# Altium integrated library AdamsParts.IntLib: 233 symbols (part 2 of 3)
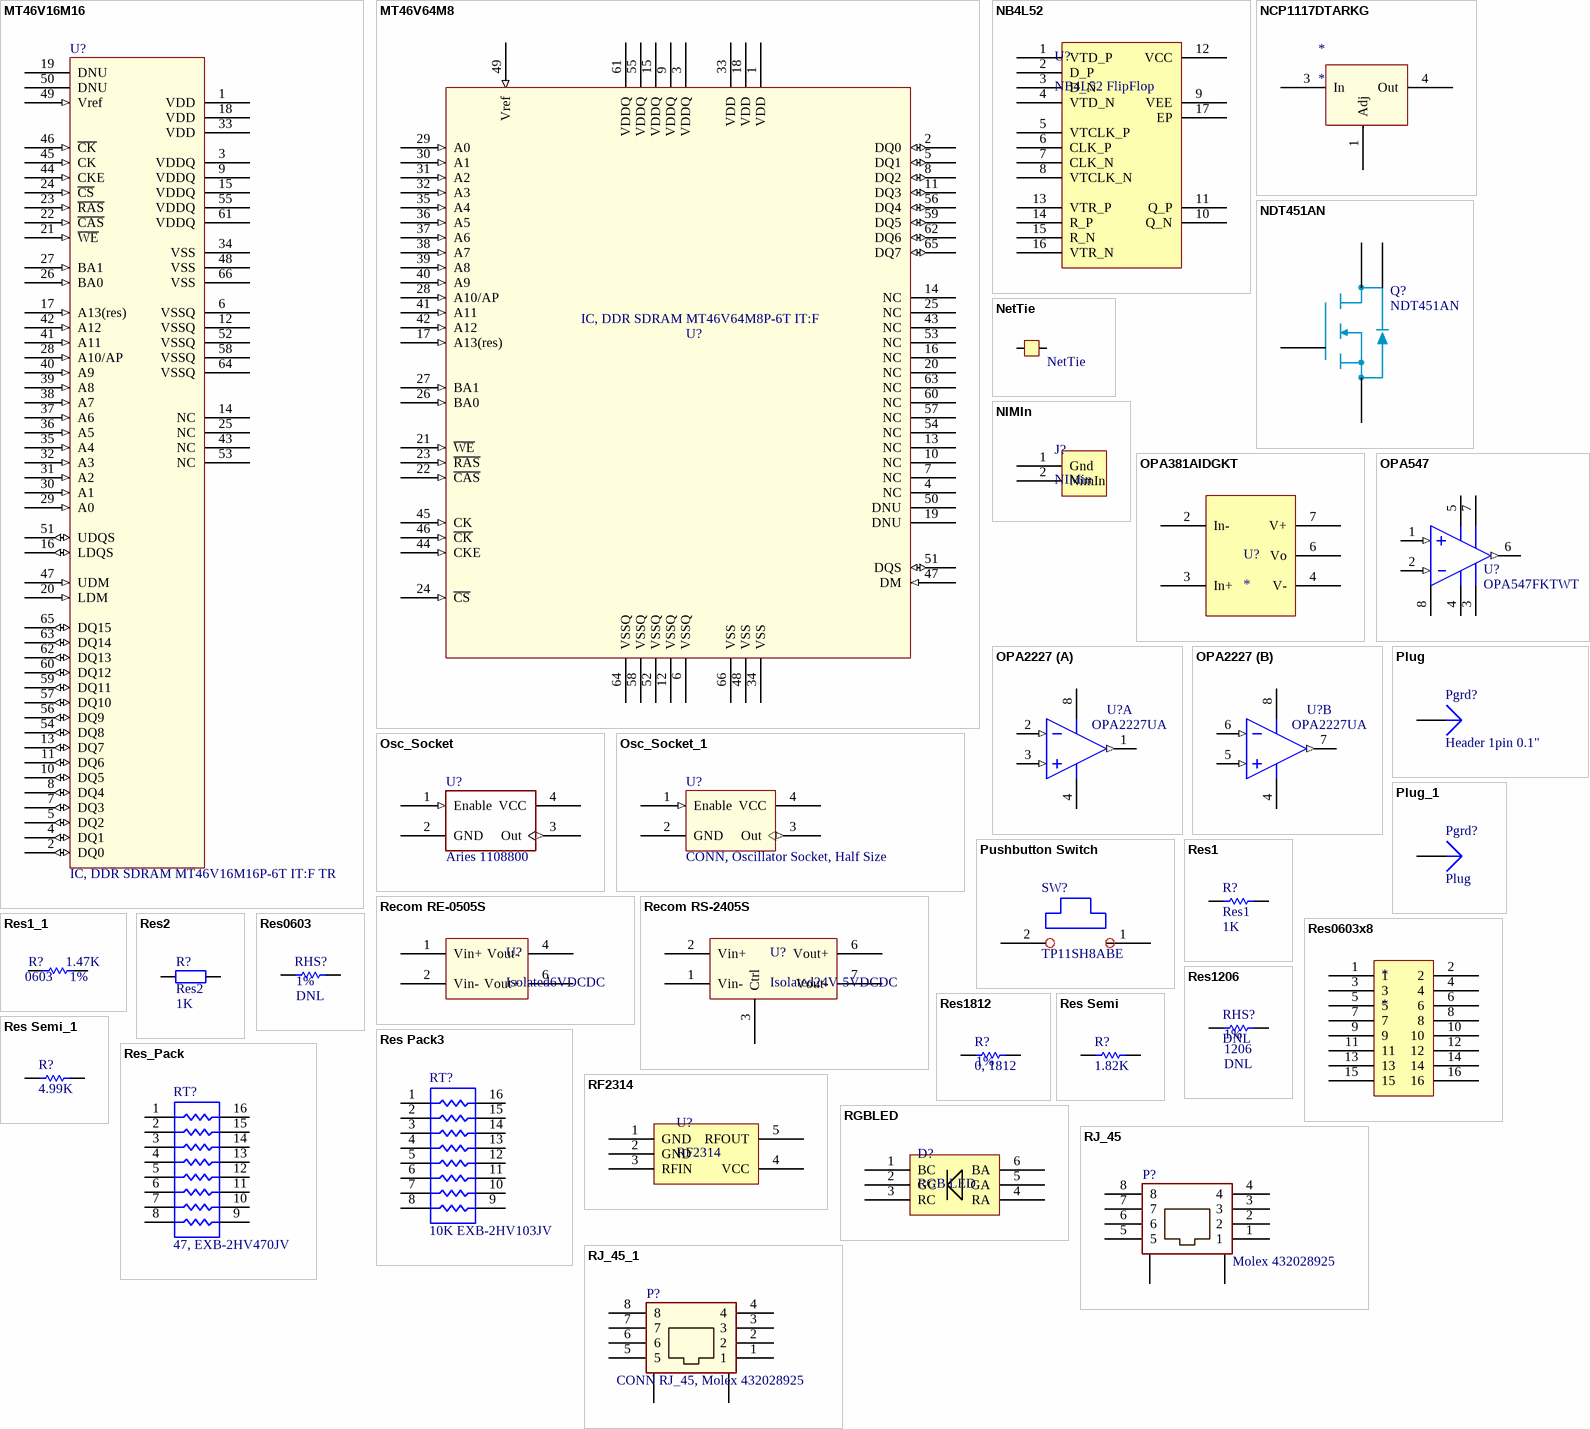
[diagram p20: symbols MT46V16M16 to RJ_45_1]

## OPA547
designator U?, comment OPA547FKTWT
Amp, High-Voltage, High-Current Op Amp; Manufacturer: Texas Instruments
footprint D2PAK-7PIN
pins: 1 IN+ (in), 2 IN- (in), 3 Ilim, 4 Vss (power), 5 Vcc (power), 6 OUT (out), 7 E/S, 8 SH (power)

## OPA2227
designator U?, comment OPA2227UA
Amp, High Precision, Low Noise  Op Amp; Manufacturer: Texas Instruments
footprint SO8
part A pins: 1 OUT (out), 2 IN- (in), 3 IN+ (in), 4 GND (power), 8 VDD (power)
part B pins: 4 GND (power), 5 IN+ (in), 6 IN- (in), 7 OUT (out), 8 VDD (power)

## Osc_Socket
designator U?, comment Aries 1108800
CONN, Oscillator Socket, Half Size; Manufacturer: Aries Electronics
footprint XTAL-OSC/DIP8 (Footprint not found)
pins: 1 Enable (in), 2 GND (power), 3 Out (out), 4 VCC (power)

## Osc_Socket_1
designator U?, comment CONN, Oscillator Socket, Half Size
1108800 ARIES Oscillator Socket
footprint DIP_Osc
pins: 1 Enable (in), 2 GND (power), 3 Out (out), 4 VCC (power)

## Plug
designator Pgrd?, comment Header 1pin 0.1"
Header, 0.1"  1-Pin straight (Any equivalent - may need to be value added); Manufacturer: Digikey; Manufacturers P/N: A26508-01-ND
footprint PIN1
signal-integrity model Connector
pins: 1

## Plug_1
designator Pgrd?, comment Plug
footprint PIN1 (Connector; Plug)
signal-integrity model Connector
pins: 1

## Pushbutton Switch
designator SW?, comment TP11SH8ABE
Switch, Pushbutton FrontPanel; Manufacturer: C&K Components
footprint TP11SH8ABE
pins: 1, 2

## Recom RE-0505S
designator U?, comment Isolated6VDCDC
Isolated 6V DC-DC
footprint RECOM_DCDC_SIP (DC-DC Converter)
pins: 1 Vin+, 2 Vin-, 4 Vout-, 6 Vout+

## Recom RS-2405S
designator U?, comment Isolated24V-5VDCDC
18-36V input, 5V output
footprint RECOM_RS-2405S (DC-DC Converter)
pins: 1 Vin-, 2 Vin+, 3 Ctrl, 5 NC hidden, 6 Vout+, 7 Vout-, 8 NC hidden

## Res1
designator R?  value 1K
Resistor
simulation model RESISTOR (Resistor)
signal-integrity model Res
footprint Model Name (Footprint not found)
footprint Model Name (Footprint not found)
footprint AXIAL-0.3 (Axial Device, Thru-Hole; 2 Leads; 0.3 in Pin Spacing)
footprint AXIAL-0.4 (Axial Device, Thru-Hole; 2 Leads; 0.4 in Pin Spacing)
footprint AXIAL-0.5 (Axial Device, Thru-Hole; 2 Leads; 0.5 in Pin Spacing)
footprint AXIAL-0.6 (Axial Device, Thru-Hole; 2 Leads; 0.6 in Pin Spacing)
footprint AXIAL-0.7 (Axial Device, Thru-Hole; 2 Leads; 0.7 in Pin Spacing)
footprint AXIAL-0.8 (Axial Device, Thru-Hole; 2 Leads; 0.8 in Pin Spacing)
footprint AXIAL-0.9 (Axial Device, Thru-Hole; 2 Leads; 0.9 in Pin Spacing)
footprint AXIAL-1.0 (Axial Device, Thru-Hole; 2 Leads; 1.0 in Pin Spacing)
footprint Model Name (Footprint not found)
pins: 1, 2

## Res1_1
designator R?, comment 1.47K  Param: 1%  Footprint: 0603
RES 1.47K OHM 1/10W 1% 0603 SMD; Manufacturer: Vishay/Dale; Manufacturers P/N: CRCW06031K47FKEA; Param1: 100ppm/C
simulation model RESISTOR (Resistor)
signal-integrity model Res
footprint 0603
pins: 1, 2

## Res2
designator R?  value 1K
Resistor
footprint AXIAL-0.4 (Axial Device, Thru-Hole; 2 Leads; 0.4 in Pin Spacing)
simulation model RESISTOR (Resistor)
signal-integrity model Res
pins: 1, 2

## Res0603
designator RHS?  value DNL  Param: 1%
Resistor; Param1: 100ppm/C
simulation model RESISTOR (Resistor)
signal-integrity model Res
footprint 0603
footprint 0805
pins: 1, 2

## Res0603x8
designator *
pins: 1, 2, 3, 4, 5, 6, 7, 8, 9, 10, 11, 12, 13, 14, 15, 16

## Res1206
designator RHS?, comment DNL  Param: 1%  Footprint: 1206
Resistor; Param1: 100ppm/C
simulation model RESISTOR (Resistor)
signal-integrity model Res
footprint CR1608-0603M (Chip Resistor; Body 1.6 x 0.8 mm (LxW typ))
footprint 1206
pins: 1, 2

## Res1812
designator R?, comment 0, 1812  Param: 1%
Resistor; Param1: 100ppm/C; Value: DNL
simulation model RESISTOR (Resistor)
signal-integrity model Res
pins: 1, 2

## Res Pack3
designator RT?, comment 10K EXB-2HV103JV
Isolated Resistor Network
footprint SO-G16/Z8.5 (Small Outline; 16 Leads; Body Width 5.6 mm; Pitch 1.27 mm)
simulation model respack_8 (Spice Subcircuit)
footprint 0402_Array_2HV
pins: 1, 2, 3, 4, 5, 6, 7, 8, 9, 10, 11, 12, 13, 14, 15, 16

## Res Semi
designator R?, comment 1.82K
RES 1.82K OHM 1/10W 1% 0603 SMD (or Equivalent); Manufacturer: Vishay/Dale; Manufacturers P/N: CRCW06031K82FKEA
footprint CR1608-0603
simulation model RES (Semiconductor Resistor)
signal-integrity model Res Semi
pins: 1, 2

## Res Semi_1
designator R?, comment 4.99K
Resistor 0603
footprint AXIAL-0.5 (Semiconductor Resistor; 2 Leads)
footprint CR1005-0402 (Chip Resistor; Body 1.1 x 0.5 mm (LxW typ))
footprint CR1608-0603 (Chip Resistor; Body 1.6 x 0.8 mm (LxW typ))
footprint CR2012-0805 (Chip Resistor; Body 2.0 x 1.3 mm (LxW typ))
footprint CR3216-1206 (Chip Resistor; Body 3.2 x 1.6 mm (LxW typ))
simulation model RES (Semiconductor Resistor)
signal-integrity model Res Semi
pins: 1, 2

## Res_Pack
designator RT?, comment 47, EXB-2HV470JV
8x 0402 RES ARRAY 47 OHM 5%  SMD; Manufacturer: Panasonic - ECG
footprint 0402_Array_2HV
pins: 1, 2, 3, 4, 5, 6, 7, 8, 9, 10, 11, 12, 13, 14, 15, 16

## RF2314
designator U?
footprint RF2314 (SOT23, 5-Leads, Body 2.9x3.0mm (max), Pitch 0.95mm, IPC Medium Density)
pins: 1 GND, 2 GND, 3 RFIN, 4 VCC, 5 RFOUT

## RGBLED
designator D?, comment RGB LED
footprint RGBLED
pins: 1 BC, 2 GC, 3 RC, 4 RA, 5 GA, 6 BA

## RJ_45
designator P?, comment Molex 432028925
CONN, RJ45; Manufacturers P/N: 0432028925
footprint RJ45
pins: 1, 2, 3, 4, 5, 6, 7, 8, 9 GND (power), 10 GND (power)

## RJ_45_1
designator P?, comment CONN RJ_45, Molex 432028925
Molex 432028925
footprint RJ45 (Regular network RJ45)
pins: 1, 2, 3, 4, 5, 6, 7, 8, 9 GND (power), 10 GND (power)

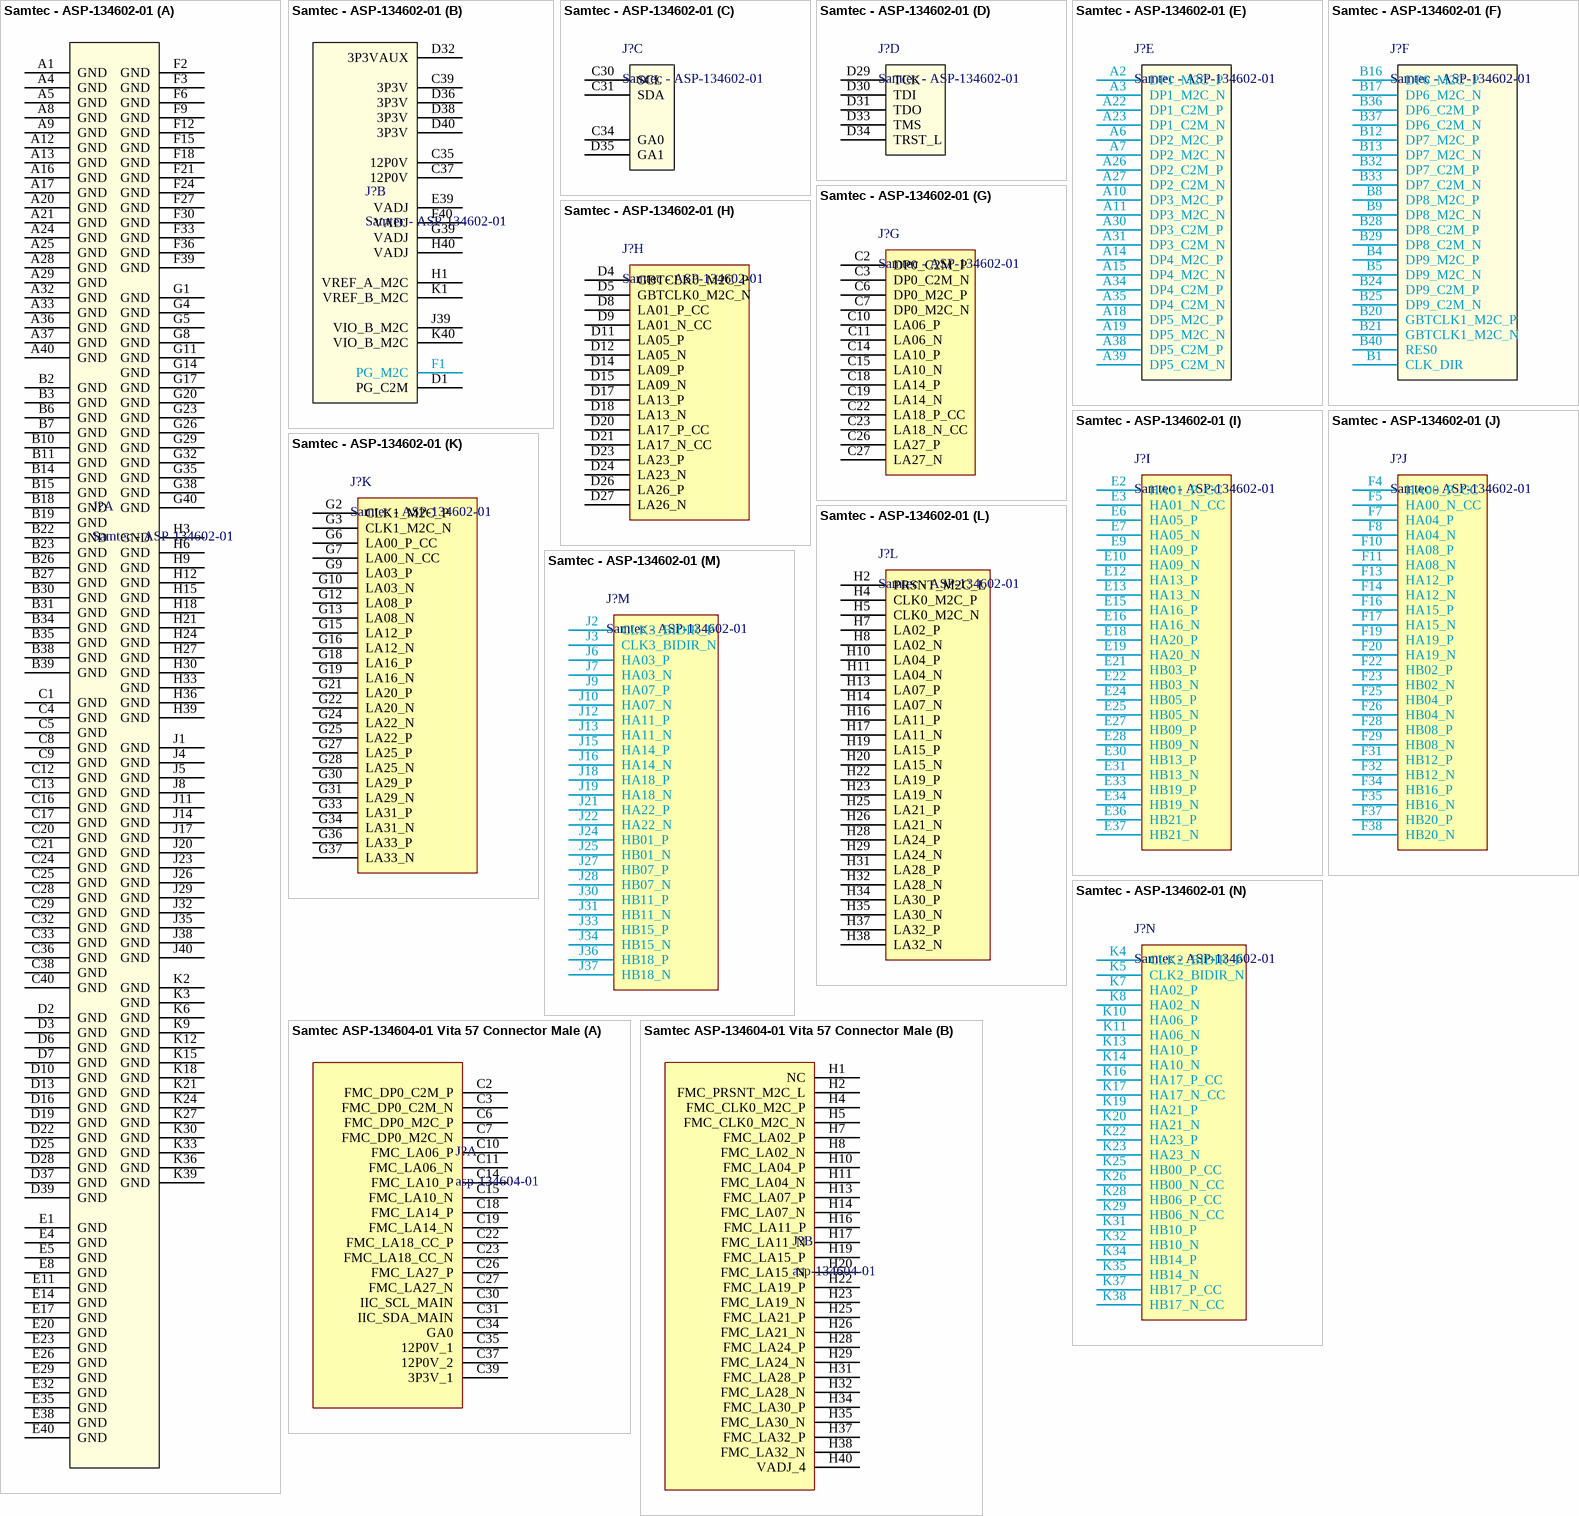
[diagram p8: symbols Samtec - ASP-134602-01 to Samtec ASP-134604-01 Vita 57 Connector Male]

## Samtec - ASP-134602-01
designator J?
footprint FCM-ASP_134602-01 (400pin FCM connector VITA)
part A pins: A1 GND, A4 GND, A5 GND, A8 GND, A9 GND, A12 GND, A13 GND, A16 GND, A17 GND, A20 GND, A21 GND, A24 GND, A25 GND, A28 GND, A29 GND, A32 GND, A33 GND, A36 GND, A37 GND, A40 GND, B2 GND, B3 GND, B6 GND, B7 GND, B10 GND, B11 GND, B14 GND, B15 GND, B18 GND, B19 GND, B22 GND, B23 GND, B26 GND, B27 GND, B30 GND, B31 GND, B34 GND, B35 GND, B38 GND, B39 GND, C1 GND, C4 GND, C5 GND, C8 GND, C9 GND, C12 GND, C13 GND, C16 GND, C17 GND, C20 GND, C21 GND, C24 GND, C25 GND, C28 GND, C29 GND, C32 GND, C33 GND, C36 GND, C38 GND, C40 GND, D2 GND, D3 GND, D6 GND, D7 GND, D10 GND, D13 GND, D16 GND, D19 GND, D22 GND, D25 GND, D28 GND, D37 GND, D39 GND, E1 GND, E4 GND, E5 GND, E8 GND, E11 GND, E14 GND, E17 GND, E20 GND, E23 GND, E26 GND, E29 GND, E32 GND, E35 GND, E38 GND, E40 GND, F2 GND, F3 GND, F6 GND, F9 GND, F12 GND, F15 GND, F18 GND, F21 GND, F24 GND, F27 GND, F30 GND, F33 GND, F36 GND, F39 GND, G1 GND, G4 GND, G5 GND, G8 GND, G11 GND, G14 GND, G17 GND, G20 GND, G23 GND, G26 GND, G29 GND, G32 GND, G35 GND, G38 GND, G40 GND, H3 GND, H6 GND, H9 GND, H12 GND, H15 GND, H18 GND, H21 GND, H24 GND, H27 GND, H30 GND, H33 GND, H36 GND, H39 GND, J1 GND, J4 GND, J5 GND, J8 GND, J11 GND, J14 GND, J17 GND, J20 GND, J23 GND, J26 GND, J29 GND, J32 GND, J35 GND, J38 GND, J40 GND, K2 GND, K3 GND, K6 GND, K9 GND, K12 GND, K15 GND, K18 GND, K21 GND, K24 GND, K27 GND, K30 GND, K33 GND, K36 GND, K39 GND
part B pins: C35 12P0V, C37 12P0V, C39 3P3V, D1 PG_C2M, D32 3P3VAUX, D36 3P3V, D38 3P3V, D40 3P3V, E39 VADJ, F1 PG_M2C, F40 VADJ, G39 VADJ, H1 VREF_A_M2C, H40 VADJ, J39 VIO_B_M2C, K1 VREF_B_M2C, K40 VIO_B_M2C
part C pins: C30 SCL, C31 SDA, C34 GA0, D35 GA1
part D pins: D29 TCK, D30 TDI, D31 TDO, D33 TMS, D34 TRST_L
part E pins: A2 DP1_M2C_P, A3 DP1_M2C_N, A6 DP2_M2C_P, A7 DP2_M2C_N, A10 DP3_M2C_P, A11 DP3_M2C_N, A14 DP4_M2C_P, A15 DP4_M2C_N, A18 DP5_M2C_P, A19 DP5_M2C_N, A22 DP1_C2M_P, A23 DP1_C2M_N, A26 DP2_C2M_P, A27 DP2_C2M_N, A30 DP3_C2M_P, A31 DP3_C2M_N, A34 DP4_C2M_P, A35 DP4_C2M_N, A38 DP5_C2M_P, A39 DP5_C2M_N
part F pins: B1 CLK_DIR, B4 DP9_M2C_P, B5 DP9_M2C_N, B8 DP8_M2C_P, B9 DP8_M2C_N, B12 DP7_M2C_P, B13 DP7_M2C_N, B16 DP6_M2C_P, B17 DP6_M2C_N, B20 GBTCLK1_M2C_P, B21 GBTCLK1_M2C_N, B24 DP9_C2M_P, B25 DP9_C2M_N, B28 DP8_C2M_P, B29 DP8_C2M_N, B32 DP7_C2M_P, B33 DP7_C2M_N, B36 DP6_C2M_P, B37 DP6_C2M_N, B40 RES0
part G pins: C2 DP0_C2M_P, C3 DP0_C2M_N, C6 DP0_M2C_P, C7 DP0_M2C_N, C10 LA06_P, C11 LA06_N, C14 LA10_P, C15 LA10_N, C18 LA14_P, C19 LA14_N, C22 LA18_P_CC, C23 LA18_N_CC, C26 LA27_P, C27 LA27_N
part H pins: D4 GBTCLK0_M2C_P, D5 GBTCLK0_M2C_N, D8 LA01_P_CC, D9 LA01_N_CC, D11 LA05_P, D12 LA05_N, D14 LA09_P, D15 LA09_N, D17 LA13_P, D18 LA13_N, D20 LA17_P_CC, D21 LA17_N_CC, D23 LA23_P, D24 LA23_N, D26 LA26_P, D27 LA26_N
part I pins: E2 HA01_P_CC, E3 HA01_N_CC, E6 HA05_P, E7 HA05_N, E9 HA09_P, E10 HA09_N, E12 HA13_P, E13 HA13_N, E15 HA16_P, E16 HA16_N, E18 HA20_P, E19 HA20_N, E21 HB03_P, E22 HB03_N, E24 HB05_P, E25 HB05_N, E27 HB09_P, E28 HB09_N, E30 HB13_P, E31 HB13_N, E33 HB19_P, E34 HB19_N, E36 HB21_P, E37 HB21_N
part J pins: F4 HA00_P_CC, F5 HA00_N_CC, F7 HA04_P, F8 HA04_N, F10 HA08_P, F11 HA08_N, F13 HA12_P, F14 HA12_N, F16 HA15_P, F17 HA15_N, F19 HA19_P, F20 HA19_N, F22 HB02_P, F23 HB02_N, F25 HB04_P, F26 HB04_N, F28 HB08_P, F29 HB08_N, F31 HB12_P, F32 HB12_N, F34 HB16_P, F35 HB16_N, F37 HB20_P, F38 HB20_N
part K pins: G2 CLK1_M2C_P, G3 CLK1_M2C_N, G6 LA00_P_CC, G7 LA00_N_CC, G9 LA03_P, G10 LA03_N, G12 LA08_P, G13 LA08_N, G15 LA12_P, G16 LA12_N, G18 LA16_P, G19 LA16_N, G21 LA20_P, G22 LA20_N, G24 LA22_N, G25 LA22_P, G27 LA25_P, G28 LA25_N, G30 LA29_P, G31 LA29_N, G33 LA31_P, G34 LA31_N, G36 LA33_P, G37 LA33_N
part L pins: H2 PRSNT_M2C_L, H4 CLK0_M2C_P, H5 CLK0_M2C_N, H7 LA02_P, H8 LA02_N, H10 LA04_P, H11 LA04_N, H13 LA07_P, H14 LA07_N, H16 LA11_P, H17 LA11_N, H19 LA15_P, H20 LA15_N, H22 LA19_P, H23 LA19_N, H25 LA21_P, H26 LA21_N, H28 LA24_P, H29 LA24_N, H31 LA28_P, H32 LA28_N, H34 LA30_P, H35 LA30_N, H37 LA32_P, H38 LA32_N
part M pins: J2 CLK3_BIDIR_P, J3 CLK3_BIDIR_N, J6 HA03_P, J7 HA03_N, J9 HA07_P, J10 HA07_N, J12 HA11_P, J13 HA11_N, J15 HA14_P, J16 HA14_N, J18 HA18_P, J19 HA18_N, J21 HA22_P, J22 HA22_N, J24 HB01_P, J25 HB01_N, J27 HB07_P, J28 HB07_N, J30 HB11_P, J31 HB11_N, J33 HB15_P, J34 HB15_N, J36 HB18_P, J37 HB18_N
part N pins: K4 CLK2_BIDIR_P, K5 CLK2_BIDIR_N, K7 HA02_P, K8 HA02_N, K10 HA06_P, K11 HA06_N, K13 HA10_P, K14 HA10_N, K16 HA17_P_CC, K17 HA17_N_CC, K19 HA21_P, K20 HA21_N, K22 HA23_P, K23 HA23_N, K25 HB00_P_CC, K26 HB00_N_CC, K28 HB06_P_CC, K29 HB06_N_CC, K31 HB10_P, K32 HB10_N, K34 HB14_P, K35 HB14_N, K37 HB17_P_CC, K38 HB17_N_CC

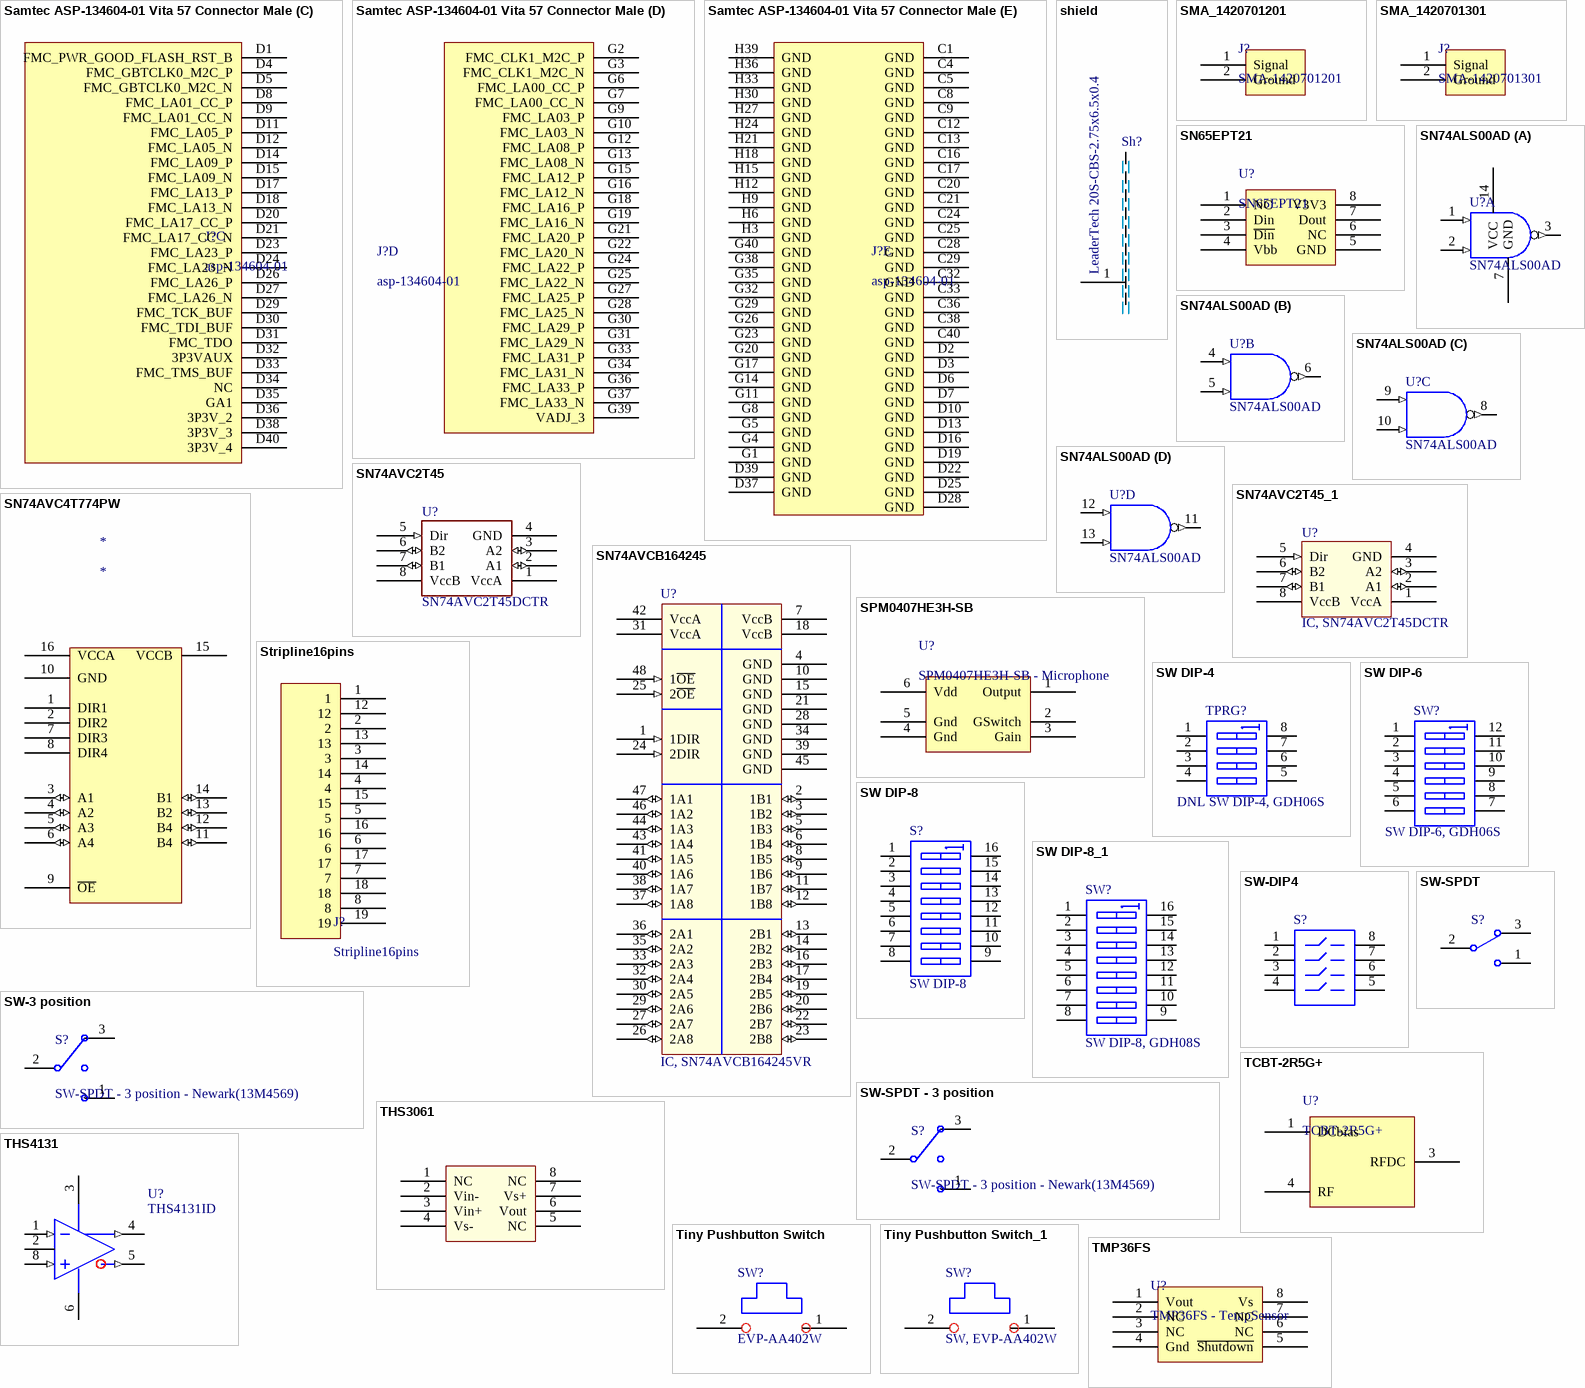
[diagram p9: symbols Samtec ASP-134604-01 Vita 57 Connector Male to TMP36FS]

## Samtec ASP-134604-01 Vita 57 Connector Male
designator J?, comment asp-134604-01
footprint FCM-ASP_134603-01 (160pin FCM connector VITA)
part A pins: C2 FMC_DP0_C2M_P, C3 FMC_DP0_C2M_N, C6 FMC_DP0_M2C_P, C7 FMC_DP0_M2C_N, C10 FMC_LA06_P, C11 FMC_LA06_N, C14 FMC_LA10_P, C15 FMC_LA10_N, C18 FMC_LA14_P, C19 FMC_LA14_N, C22 FMC_LA18_CC_P, C23 FMC_LA18_CC_N, C26 FMC_LA27_P, C27 FMC_LA27_N, C30 IIC_SCL_MAIN, C31 IIC_SDA_MAIN, C34 GA0, C35 12P0V_1, C37 12P0V_2, C39 3P3V_1
part B pins: H1 NC, H2 FMC_PRSNT_M2C_L, H4 FMC_CLK0_M2C_P, H5 FMC_CLK0_M2C_N, H7 FMC_LA02_P, H8 FMC_LA02_N, H10 FMC_LA04_P, H11 FMC_LA04_N, H13 FMC_LA07_P, H14 FMC_LA07_N, H16 FMC_LA11_P, H17 FMC_LA11_N, H19 FMC_LA15_P, H20 FMC_LA15_N, H22 FMC_LA19_P, H23 FMC_LA19_N, H25 FMC_LA21_P, H26 FMC_LA21_N, H28 FMC_LA24_P, H29 FMC_LA24_N, H31 FMC_LA28_P, H32 FMC_LA28_N, H34 FMC_LA30_P, H35 FMC_LA30_N, H37 FMC_LA32_P, H38 FMC_LA32_N, H40 VADJ_4
part C pins: D1 FMC_PWR_GOOD_FLASH_RST_B, D4 FMC_GBTCLK0_M2C_P, D5 FMC_GBTCLK0_M2C_N, D8 FMC_LA01_CC_P, D9 FMC_LA01_CC_N, D11 FMC_LA05_P, D12 FMC_LA05_N, D14 FMC_LA09_P, D15 FMC_LA09_N, D17 FMC_LA13_P, D18 FMC_LA13_N, D20 FMC_LA17_CC_P, D21 FMC_LA17_CC_N, D23 FMC_LA23_P, D24 FMC_LA23_N, D26 FMC_LA26_P, D27 FMC_LA26_N, D29 FMC_TCK_BUF, D30 FMC_TDI_BUF, D31 FMC_TDO, D32 3P3VAUX, D33 FMC_TMS_BUF, D34 NC, D35 GA1, D36 3P3V_2, D38 3P3V_3, D40 3P3V_4
part D pins: G2 FMC_CLK1_M2C_P, G3 FMC_CLK1_M2C_N, G6 FMC_LA00_CC_P, G7 FMC_LA00_CC_N, G9 FMC_LA03_P, G10 FMC_LA03_N, G12 FMC_LA08_P, G13 FMC_LA08_N, G15 FMC_LA12_P, G16 FMC_LA12_N, G18 FMC_LA16_P, G19 FMC_LA16_N, G21 FMC_LA20_P, G22 FMC_LA20_N, G24 FMC_LA22_P, G25 FMC_LA22_N, G27 FMC_LA25_P, G28 FMC_LA25_N, G30 FMC_LA29_P, G31 FMC_LA29_N, G33 FMC_LA31_P, G34 FMC_LA31_N, G36 FMC_LA33_P, G37 FMC_LA33_N, G39 VADJ_3
part E pins: C1 GND, C4 GND, C5 GND, C8 GND, C9 GND, C12 GND, C13 GND, C16 GND, C17 GND, C20 GND, C21 GND, C24 GND, C25 GND, C28 GND, C29 GND, C32 GND, C33 GND, C36 GND, C38 GND, C40 GND, D2 GND, D3 GND, D6 GND, D7 GND, D10 GND, D13 GND, D16 GND, D19 GND, D22 GND, D25 GND, D28 GND, D37 GND, D39 GND, G1 GND, G4 GND, G5 GND, G8 GND, G11 GND, G14 GND, G17 GND, G20 GND, G23 GND, G26 GND, G29 GND, G32 GND, G35 GND, G38 GND, G40 GND, H3 GND, H6 GND, H9 GND, H12 GND, H15 GND, H18 GND, H21 GND, H24 GND, H27 GND, H30 GND, H33 GND, H36 GND, H39 GND

## shield
designator Sh?, comment LeaderTech 20S-CBS-2.75x6.5x0.4
Grounded RF Shield
footprint Shield base
pins: 1

## SMA_1420701201
designator J?, comment SMA-1420701201
Vertical SMA
footprint SMA-1420701301 (SMA 1420701301 Ghz Connector)
footprint SMA-1420701201 (SMA 1420701201 Ghz Connector)
pins: 1 Signal, 2 Ground

## SMA_1420701301
designator J?, comment SMA-1420701301
Horizontal SMA
footprint SMA-1420701301 (SMA 1420701301 Ghz Connector)
pins: 1 Signal, 2 Ground

## SN65EPT21
designator U?
footprint SO8/L200
pins: 1 NC, 2 Din, 3 ~{Din}, 4 Vbb, 5 GND, 6 NC, 7 Dout, 8 V3V3

## SN74ALS00AD
designator U?
Quadruple 2-Input Positive-NAND Gate
footprint D014_N (SOIC, 14-Leads, Body 8.7x3.9mm, Pitch 1.27mm, IPC Medium Density)
footprint D014_L (SOIC, 14-Leads, Body 8.7x3.9mm, Pitch 1.27mm, IPC High Density)
footprint D014_M (SOIC, 14-Leads, Body 8.7x3.9mm, Pitch 1.27mm, IPC Low Density)
signal-integrity model SN74ALS00AD
part A pins: 1 A (in), 2 B (in), 3 Y (out), 7 GND, 14 VCC
part B pins: 4 A (in), 5 B (in), 6 Y (out)
part C pins: 8 Y (out), 9 A (in), 10 B (in)
part D pins: 11 Y (out), 12 A (in), 13 B (in)

## SN74AVC2T45
designator U?, comment SN74AVC2T45DCTR
Transceiver, Dual-bit Dual-supply Bus; Manufacturer: Texas Instruments
footprint SM8 (Footprint not found)
pins: 1 VccA (power), 2 A1 (io), 3 A2 (io), 4 GND (power), 5 Dir (in), 6 B2 (io), 7 B1 (io), 8 VccB (power)

## SN74AVC2T45_1
designator U?, comment IC, SN74AVC2T45DCTR
Dual-bit Dual-supply Bus Transceiver
footprint TSSO3x5-G8/X.35 (Shrink Small Outline; 8 Leads; Body Width 3 mm; Pitch 0.65 mm)
pins: 1 VccA (power), 2 A1 (io), 3 A2 (io), 4 GND (power), 5 Dir (in), 6 B2 (io), 7 B1 (io), 8 VccB (power)

## SN74AVC4T774PW
designator *
footprint TSSOP16_M (TSOP, 16-Leads, Body 5x4.4mm, Pitch 0.65mm, IPC Low Density)
pins: 1 DIR1, 2 DIR2, 3 A1 (io), 4 A2 (io), 5 A3 (io), 6 A4 (io), 7 DIR3, 8 DIR4, 9 ~{OE}, 10 GND, 11 B4 (io), 12 B4 (io), 13 B2 (io), 14 B1 (io), 15 VCCB, 16 VCCA

## SN74AVCB164245
designator U?, comment IC, SN74AVCB164245VR
16-Bit Dual-Supply Bus Transceiver with CVT and 3-state
footprint DGV048 (Shrink Small Outline; 48 Leads; Body Width 4.4 mm; Pitch 0.4 mm)
pins: 1 1DIR (in), 2 1B1 (io), 3 1B2 (io), 4 GND (power), 5 1B3 (io), 6 1B4 (io), 7 VccB (power), 8 1B5 (io), 9 1B6 (io), 10 GND (power), 11 1B7 (io), 12 1B8 (io), 13 2B1 (io), 14 2B2 (io), 15 GND (power), 16 2B3 (io), 17 2B4 (io), 18 VccB (power), 19 2B5 (io), 20 2B6 (io), 21 GND (power), 22 2B7 (io), 23 2B8 (io), 24 2DIR (in), 25 2~{OE} (in), 26 2A8 (io), 27 2A7 (io), 28 GND (power), 29 2A6 (io), 30 2A5 (io), 31 VccA (power), 32 2A4 (io), 33 2A3 (io), 34 GND (power), 35 2A2 (io), 36 2A1 (io), 37 1A8 (io), 38 1A7 (io), 39 GND (power), 40 1A6 (io), 41 1A5 (io), 42 VccA (power), 43 1A4 (io), 44 1A3 (io), 45 GND (power), 46 1A2 (io), 47 1A1 (io), 48 1~{OE} (in)

## SPM0407HE3H-SB
designator U?, comment SPM0407HE3H-SB - Microphone
footprint SPM0407HE3H-SB
pins: 1 Output, 2 GSwitch, 3 Gain, 4 Gnd, 5 Gnd, 6 Vdd

## Stripline16pins
designator J?
footprint Stripline16pins (Stripline 16pins)
pins: 1, 2, 3, 4, 5, 6, 7, 8, 12, 13, 14, 15, 16, 17, 18, 19

## SW DIP-4
designator TPRG?, comment DNL SW DIP-4, GDH06S
DIP Switch, 4 Position, SPST
footprint SO-G8 (Small Outline; 8 Leads; Body Width 3.9 mm; Pitch 1.27 mm)
simulation model dpsw4 (Spice Subcircuit)
pins: 1 A1, 2 A2, 3 A3, 4 A4, 5 B4, 6 B3, 7 B2, 8 B1

## SW DIP-6
designator SW?, comment SW DIP-6, GDH06S
DIP Switch, 6 Position, SPST
footprint DIP-12/SW (DIP Switch; 12 Leads)
simulation model dpsw6 (Spice Subcircuit)
footprint DIP_SW_SM6POS (6-position DIP switch)
pins: 1 A1, 2 A2, 3 A3, 4 A4, 5 A5, 6 A6, 7 B6, 8 B5, 9 B4, 10 B3, 11 B2, 12 B1

## SW DIP-8
designator S?
DIP Switch, 8 Position, SPST; Manufacturer: Grayhill Inc; Manufacturers P/N: 97c08st
footprint DIP_SW_8WAY_SMD (DIP Switch; 16 Leads)
simulation model dpsw8 (Spice Subcircuit)
footprint SW-SO16 (Footprint not found)
pins: 1 A1, 2 A2, 3 A3, 4 A4, 5 A5, 6 A6, 7 A7, 8 A8, 9 B8, 10 B7, 11 B6, 12 B5, 13 B4, 14 B3, 15 B2, 16 B1

## SW DIP-8_1
designator SW?, comment SW DIP-8, GDH08S
DIP Switch, 8 Position, SPST
footprint DIP_SW_8WAY_SMD (DIP Switch; 16 Leads)
simulation model dpsw8 (Spice Subcircuit)
pins: 1 A1, 2 A2, 3 A3, 4 A4, 5 A5, 6 A6, 7 A7, 8 A8, 9 B8, 10 B7, 11 B6, 12 B5, 13 B4, 14 B3, 15 B2, 16 B1

## SW-3 position
designator S?, comment SW-SPDT - 3 position - Newark(13M4569)
3 Pos Toggle Switch
footprint SW-3Pos
pins: 1, 2, 3

## SW-DIP4
designator S?
DIP Switch
footprint DIP8SM (Surface Mount DIP 8 package)
pins: 1, 2, 3, 4, 5, 6, 7, 8

## SW-SPDT
designator S?
SPDT Subminiature Toggle Switch, Right Angle Mounting, Vertical Actuation
footprint TL36WW15050 (SPDT Subminiature Toggle Switch, Right Angle Mounting, Vertical Actuation)
pins: 1, 2, 3

## SW-SPDT - 3 position
designator S?, comment SW-SPDT - 3 position - Newark(13M4569)
SPDT Subminiature Toggle Switch, Right Angle Mounting, Vertical Actuation
footprint TL36WW15050 (SPDT Subminiature Toggle Switch, Right Angle Mounting, Vertical Actuation)
footprint HDR1X3
pins: 1, 2, 3

## TCBT-2R5G+
designator U?
Minicircuits 50 Ohm 20-2500Mhz RF Tee
footprint TCBT-2R5G+ (Minicircuits Bias-Tee 50 Ohm 20-2500MHz)
pins: 1 DCbias, 3 RFDC, 4 RF

## THS3061
designator *
footprint SO8/L200
pins: 1 NC, 2 Vin-, 3 Vin+, 4 Vs-, 5 NC, 6 Vout, 7 Vs+, 8 NC

## THS4131
designator U?, comment THS4131ID
Amp, FULLY-DIFFERENTIAL Op Amp; Manufacturer: Texas Instruments
simulation model ths4131 (SUBCKT)
footprint SO-G8 (SOIC)
pins: 1 (in), 2, 3 (power), 4 (out), 5 (out), 6 (power), 7 NC hidden, 8 (in)

## Tiny Pushbutton Switch
designator SW?, comment EVP-AA402W
Switch, SM pushbutton SPST; Manufacturer: Panasonic - ECG
footprint EVPAA
pins: 1, 2

## Tiny Pushbutton Switch_1
designator SW?, comment SW, EVP-AA402W
Switch, SM pushbutton SPST
footprint TP11 (Vertical 90 degree front panel pushbutton)
footprint EVPAA
footprint TP11SH8ABE
pins: 1, 2

## TMP36FS
designator U?, comment TMP36FS - TempSensor
footprint SO8/L200
pins: 1 Vout, 2 NC, 3 NC, 4 Gnd, 5 ~{Shutdown}, 6 NC, 7 NC, 8 Vs

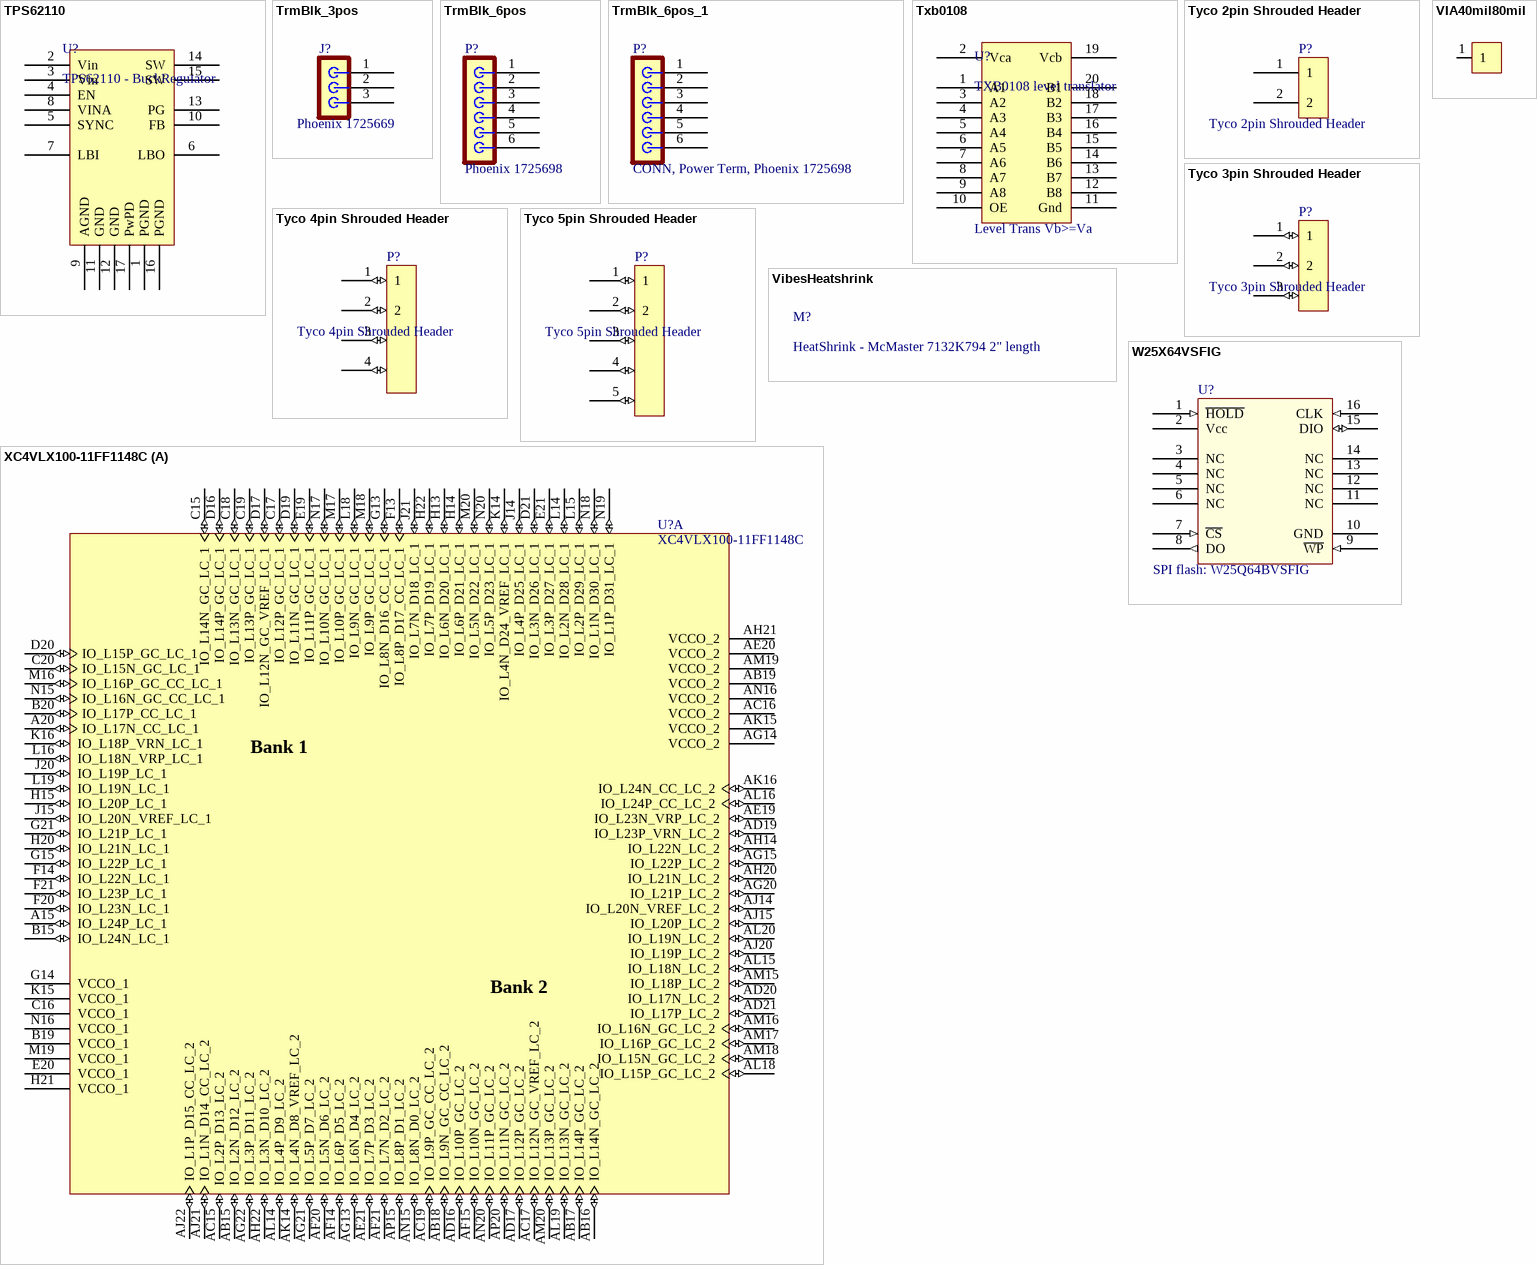
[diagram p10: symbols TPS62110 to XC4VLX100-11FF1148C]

## TPS62110
designator U?, comment TPS62110 - BuckRegulator
Buck Converter 1Mhz 1.5A
footprint RSA (S-PQFP-N16) (QFN, 16-Leads, Body 4.2x4.2mm (max), Pitch 0.65mm, IPC Medium Density)
pins: 1 PGND, 2 Vin, 3 Vin, 4 EN, 5 SYNC, 6 LBO, 7 LBI, 8 VINA, 9 AGND, 10 FB, 11 GND, 12 GND, 13 PG, 14 SW, 15 SW, 16 PGND, 17 PwPD

## TrmBlk_3pos
designator J?, comment Phoenix 1725669
CONN, MPT 0.5/3-2.54 Terminal Block; Manufacturer: Phoenix Contact; Manufacturers P/N: 1725698
footprint PHOENIX_1725669-3PIN (Footprint not found)
pins: 1, 2, 3

## TrmBlk_6pos
designator P?, comment Phoenix 1725698
CONN, MPT 0.5/6-2.54 Terminal Block; Manufacturer: Phoenix Contact
footprint TrmBlk6
pins: 1, 2, 3, 4, 5, 6

## TrmBlk_6pos_1
designator P?, comment CONN, Power Term, Phoenix 1725698
MPT 0.5/6-2.54 Terminal Block
footprint TrmBlk6 (Phoenix 6-Pos Terminal Block)
pins: 1, 2, 3, 4, 5, 6

## Txb0108
designator U?, comment TXB0108 level translator
8bit level translator - Bidirectional without directional control
footprint TSOP65P640X120-20N (TSOP, 20-Leads, Body 6.6x4.5mm (max), Pitch 0.65mm, IPC Medium Density)
pins: 1 A1, 2 Vca, 3 A2, 4 A3, 5 A4, 6 A5, 7 A6, 8 A7, 9 A8, 10 OE, 11 Gnd, 12 B8, 13 B7, 14 B6, 15 B5, 16 B4, 17 B3, 18 B2, 19 Vcb, 20 B1

## Tyco 2pin Shrouded Header
designator P?
footprint Tyco 2pin Shrouded Header
pins: 1, 2

## Tyco 3pin Shrouded Header
designator P?
footprint Tyco 3pin Shrouded Header
pins: 1 (io), 2 (io), 3 (io)

## Tyco 4pin Shrouded Header
designator P?
footprint Tyco 4pin Shrouded Header
pins: 1 (io), 2 (io), 3 (io), 4 (io)

## Tyco 5pin Shrouded Header
designator P?
footprint Tyco 5pin Shrouded Header
pins: 1 (io), 2 (io), 3 (io), 4 (io), 5 (io)

## VIA40mil80mil
designator V?  (value not drawn)
footprint VIA40mil80mil (Via with 40mil hole and 80mil diameter)
pins: 1

## VibesHeatshrink
designator M?, comment HeatShrink - McMaster 7132K794 2" length
Vibes board Heat Shrink

## W25X64VSFIG
designator U?, comment SPI flash: W25Q64BVSFIG
Manufacturer: Winbond Electronics
footprint SOIC127P1030X264-16N (SOIC, 16-Leads, Body 10.5x7.6mm (max), Pitch 1.27mm, IPC Medium Density)
footprint sol16
pins: 1 ~{HOLD} (in), 2 Vcc (power), 3 NC (hiz), 4 NC (hiz), 5 NC (hiz), 6 NC (hiz), 7 ~{CS} (in), 8 DO (out), 9 ~{WP} (in), 10 GND (power), 11 NC (hiz), 12 NC (hiz), 13 NC (hiz), 14 NC (hiz), 15 DIO (io), 16 CLK (in)

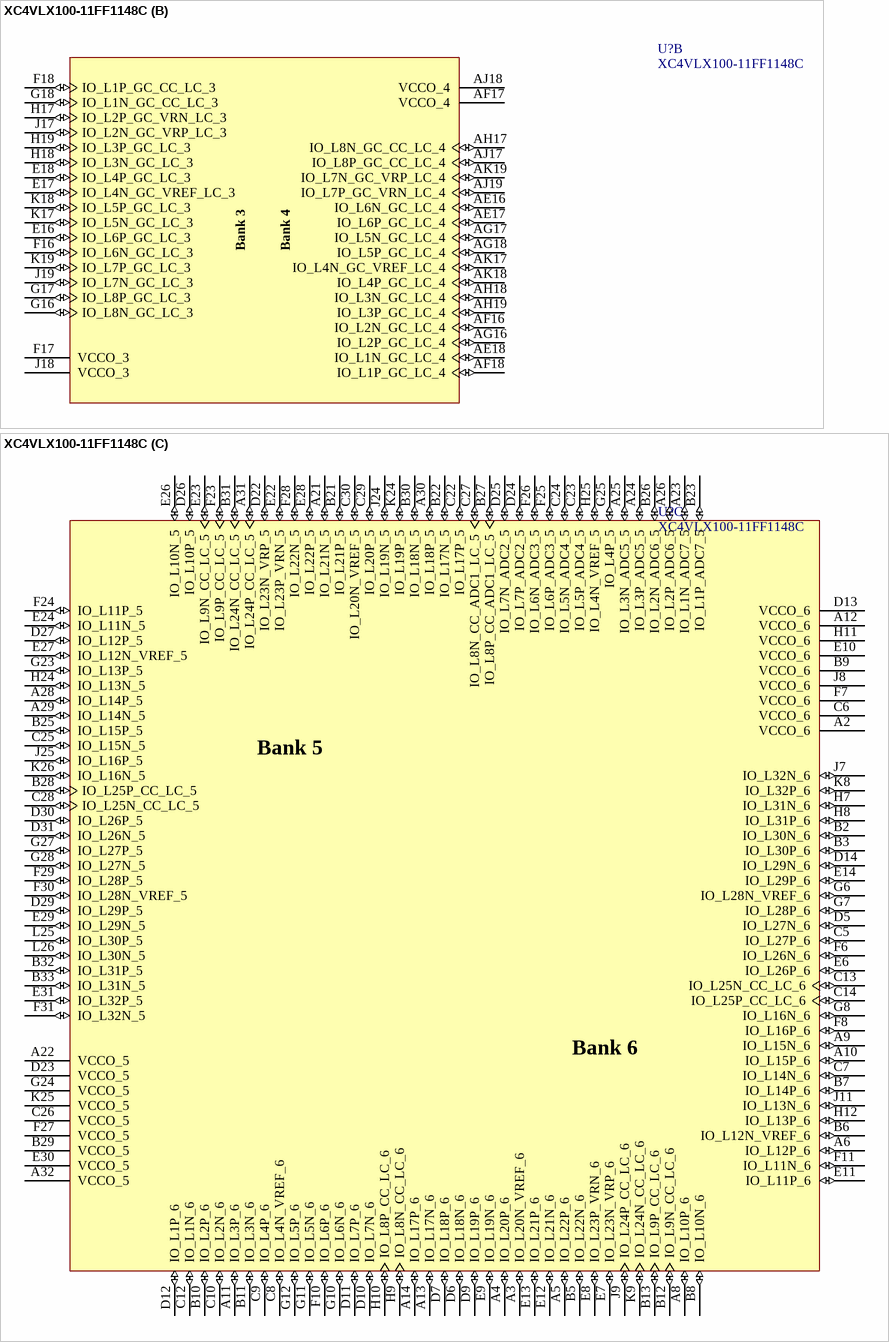
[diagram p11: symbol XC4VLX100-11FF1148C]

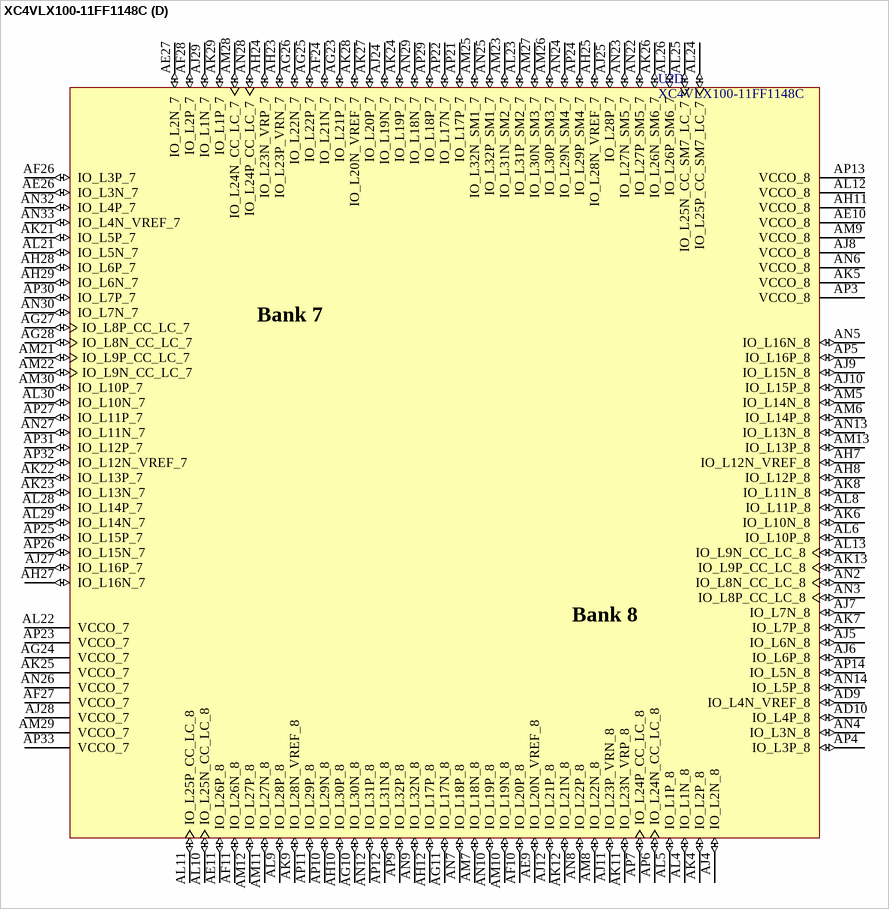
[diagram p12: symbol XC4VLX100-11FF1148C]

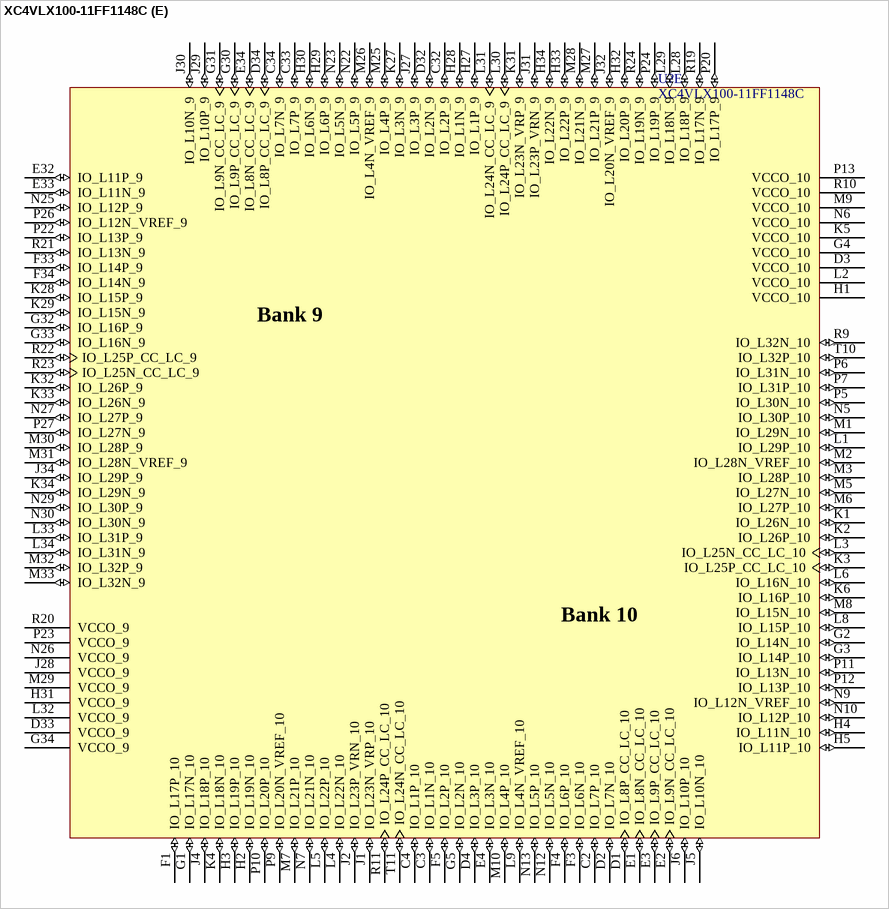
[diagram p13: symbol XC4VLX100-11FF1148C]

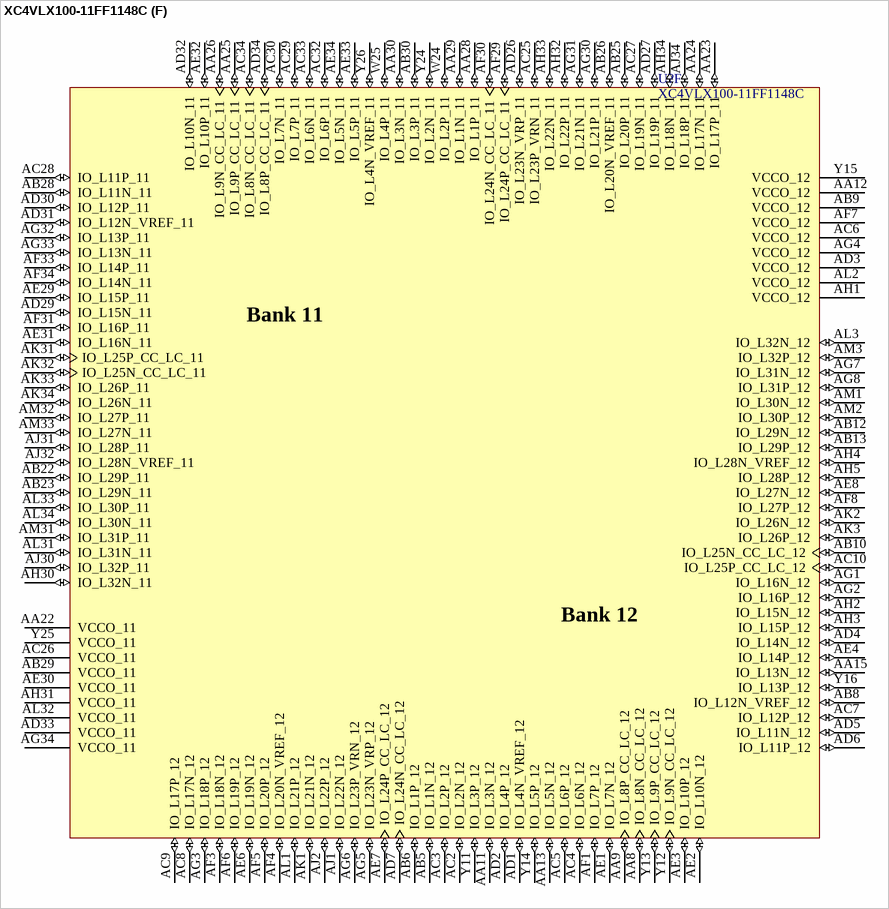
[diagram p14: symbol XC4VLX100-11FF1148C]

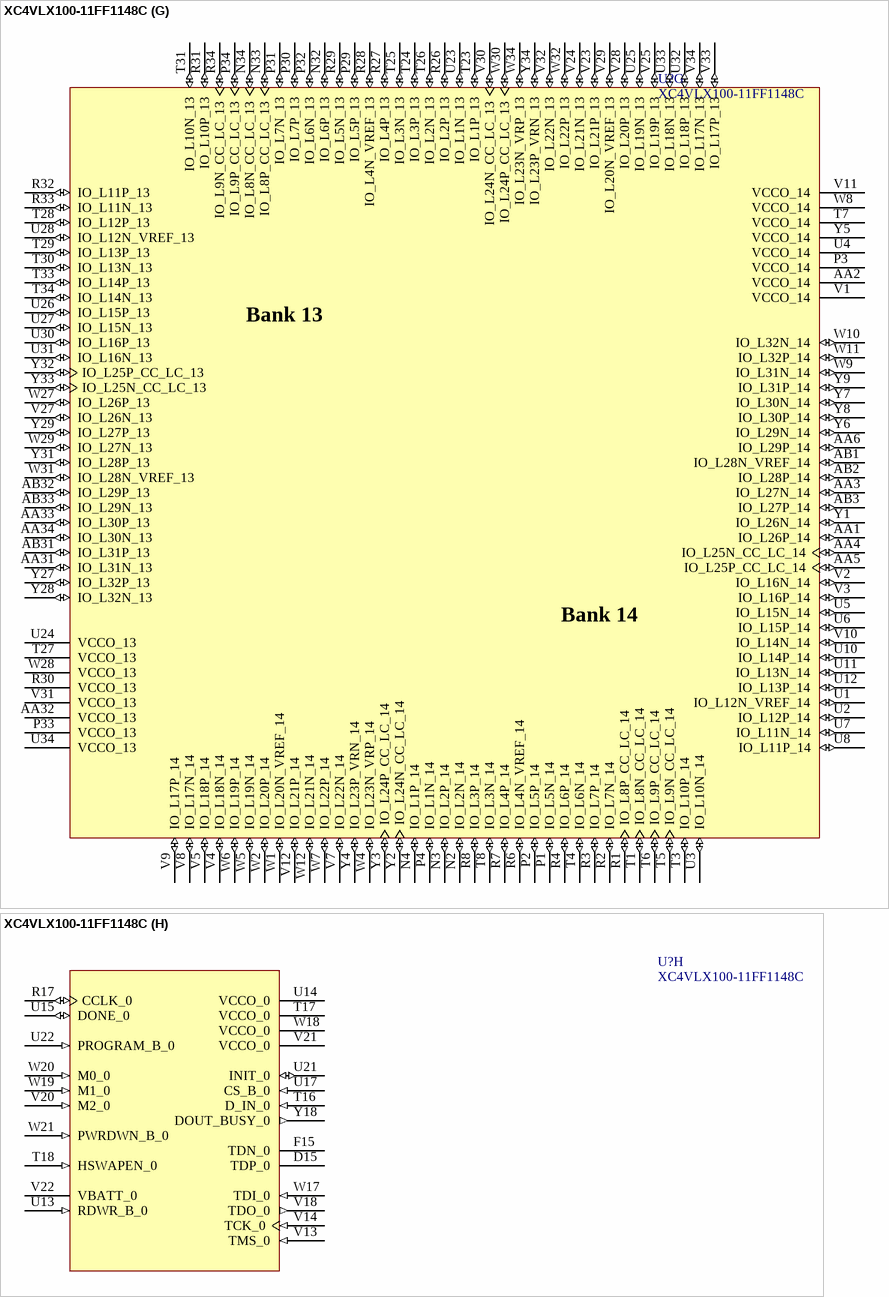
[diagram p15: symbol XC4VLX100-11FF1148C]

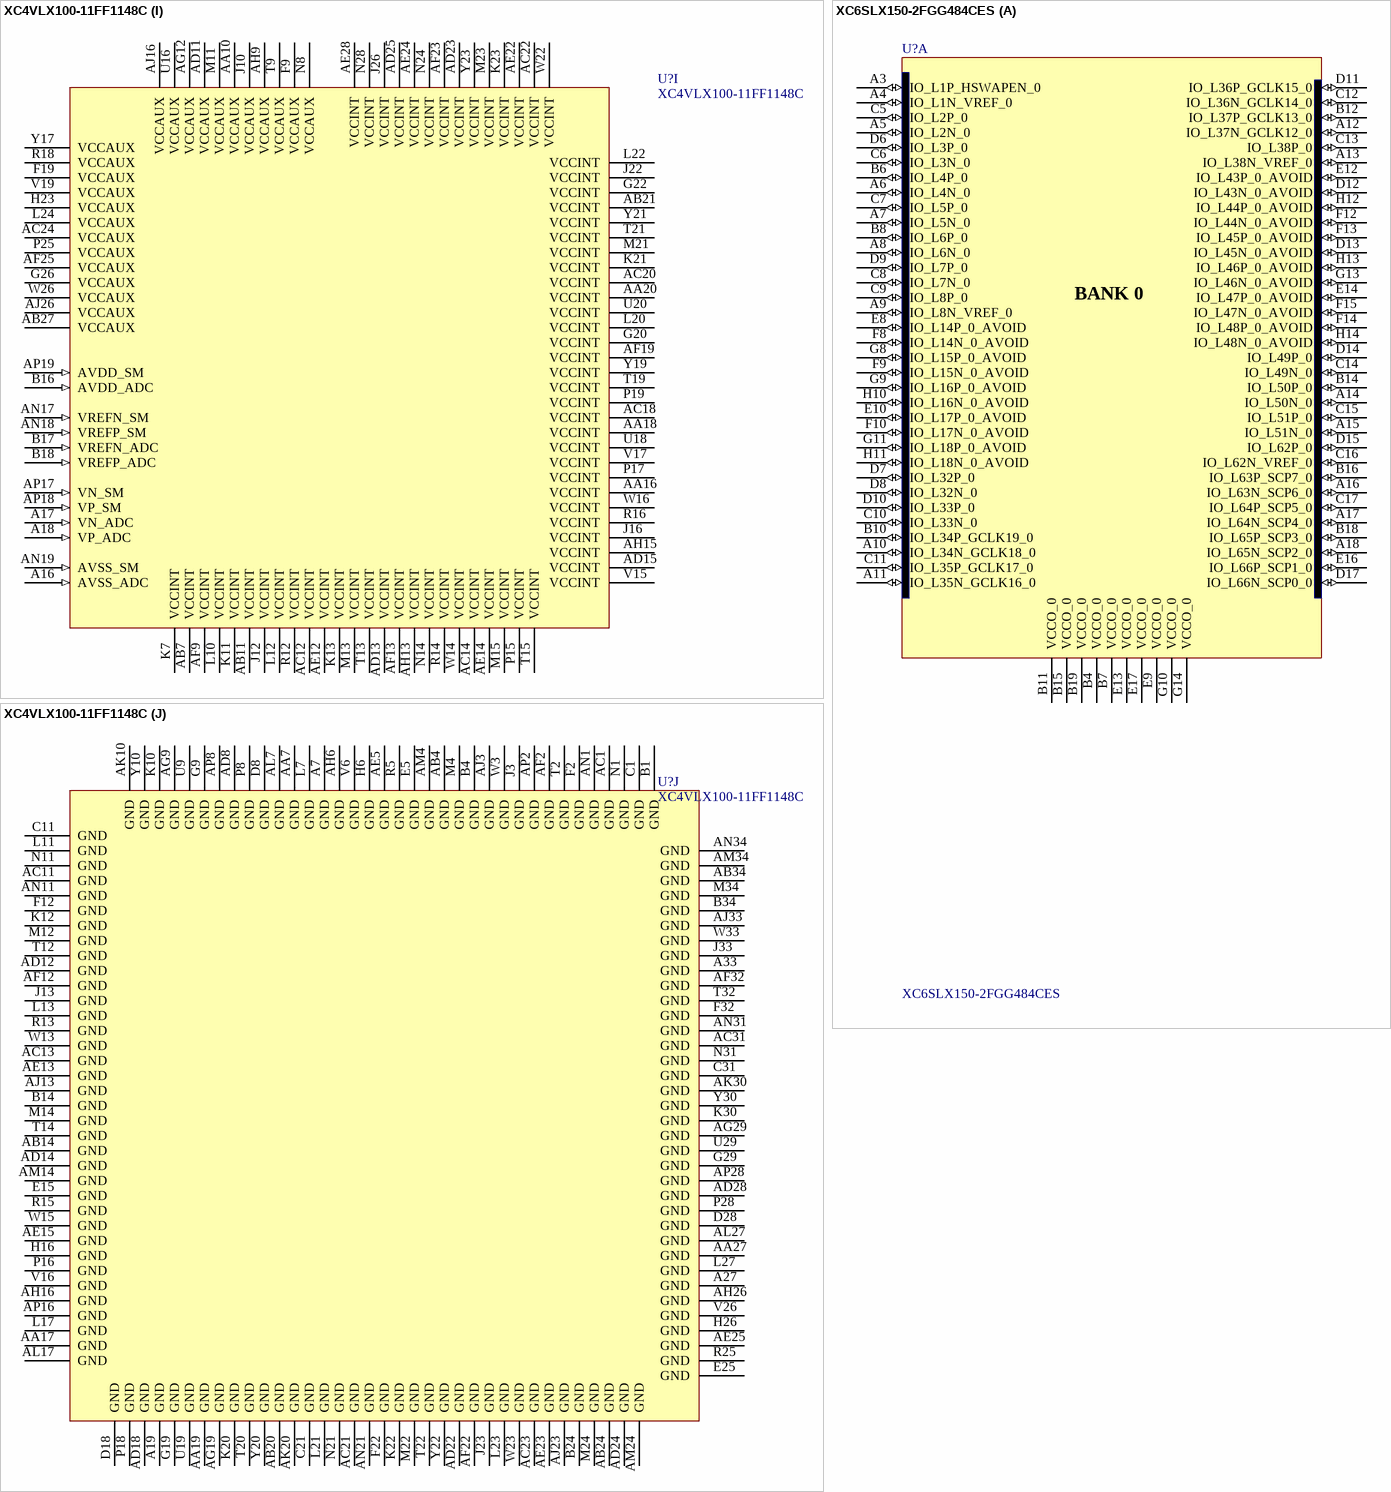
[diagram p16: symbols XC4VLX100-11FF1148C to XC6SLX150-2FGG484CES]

## XC4VLX100-11FF1148C
designator U?
Xilinx Virtex-4 LX Platform FPGA, 1148-Ball FFBGA, Speed Grade 11, 768 User I/Os, Commercial Grade; PackageDocument: ver1.0, Oct-2002
footprint FF1148 (1148-Ball Flip-Chip Fine Pitch Ball Grid Array (FF1148))
3D model XC4VLX100-FF1148 (1148-Ball Flip-Chip Fine Pitch Ball Grid Array (FF1148))
signal-integrity model XC4VLX100_FF1148 (Virtex-4)
part A pins: A15 IO_L24P_LC_1 (io), A20 IO_L17N_CC_LC_1 (io), AB15 IO_L2N_D12_LC_2 (io), AB16 IO_L14N_GC_LC_2 (io), AB17 IO_L14P_GC_LC_2 (io), AB18 IO_L9N_GC_CC_LC_2 (io), AB19 VCCO_2 (power), AC15 IO_L2P_D13_LC_2 (io), AC16 VCCO_2 (power), AC17 IO_L12N_GC_VREF_LC_2 (io), AC19 IO_L9P_GC_CC_LC_2 (io), AD16 IO_L10P_GC_LC_2 (io), AD17 IO_L12P_GC_LC_2 (io), AD19 IO_L23P_VRN_LC_2 (io), AD20 IO_L17N_LC_2 (io), AD21 IO_L17P_LC_2 (io), AE19 IO_L23N_VRP_LC_2 (io), AE20 VCCO_2 (power), AE21 IO_L7P_D3_LC_2 (io), AF14 IO_L6P_D5_LC_2 (io), AF15 IO_L10N_GC_LC_2 (io), AF20 IO_L5N_D6_LC_2 (io), AF21 IO_L7N_D2_LC_2 (io), AG13 IO_L6N_D4_LC_2 (io), AG14 VCCO_2 (power), AG15 IO_L22P_LC_2 (io), AG20 IO_L21P_LC_2 (io), AG21 IO_L5P_D7_LC_2 (io), AG22 IO_L3P_D11_LC_2 (io), AH14 IO_L22N_LC_2 (io), AH20 IO_L21N_LC_2 (io), AH21 VCCO_2 (power), AH22 IO_L3N_D10_LC_2 (io), AJ14 IO_L20N_VREF_LC_2 (io), AJ15 IO_L20P_LC_2 (io), AJ20 IO_L19P_LC_2 (io), AJ21 IO_L1N_D14_CC_LC_2 (io), AJ22 IO_L1P_D15_CC_LC_2 (io), AK14 IO_L4N_D8_VREF_LC_2 (io), AK15 VCCO_2 (power), AK16 IO_L24N_CC_LC_2 (io), AL14 IO_L4P_D9_LC_2 (io), AL15 IO_L18N_LC_2 (io), AL16 IO_L24P_CC_LC_2 (io), AL18 IO_L15P_GC_LC_2 (io), AL19 IO_L13N_GC_LC_2 (io), AL20 IO_L19N_LC_2 (io), AM15 IO_L18P_LC_2 (io), AM16 IO_L16N_GC_LC_2 (io), AM17 IO_L16P_GC_LC_2 (io), AM18 IO_L15N_GC_LC_2 (io), AM19 VCCO_2 (power), AM20 IO_L13P_GC_LC_2 (io), AN15 IO_L8N_D0_LC_2 (io), AN16 VCCO_2 (power), AN20 IO_L11P_GC_LC_2 (io), AP15 IO_L8P_D1_LC_2 (io), AP20 IO_L11N_GC_LC_2 (io), B15 IO_L24N_LC_1 (io), B19 VCCO_1 (power), B20 IO_L17P_CC_LC_1 (io), C15 IO_L14N_GC_LC_1 (io), C16 VCCO_1 (power), C17 IO_L12P_GC_LC_1 (io), C18 IO_L13N_GC_LC_1 (io), C19 IO_L13P_GC_LC_1 (io), C20 IO_L15N_GC_LC_1 (io), D16 IO_L14P_GC_LC_1 (io), D17 IO_L12N_GC_VREF_LC_1 (io), D19 IO_L11N_GC_LC_1 (io), D20 IO_L15P_GC_LC_1 (io), D21 IO_L3N_D26_LC_1 (io), E19 IO_L11P_GC_LC_1 (io), E20 VCCO_1 (power), E21 IO_L3P_D27_LC_1 (io), F13 IO_L8P_D17_CC_LC_1 (io), F14 IO_L22N_LC_1 (io), F20 IO_L23N_LC_1 (io), F21 IO_L23P_LC_1 (io), G13 IO_L8N_D16_CC_LC_1 (io), G14 VCCO_1 (power), G15 IO_L22P_LC_1 (io), G21 IO_L21P_LC_1 (io), H13 IO_L6N_D20_LC_1 (io), H14 IO_L6P_D21_LC_1 (io), H15 IO_L20P_LC_1 (io), H20 IO_L21N_LC_1 (io), H21 VCCO_1 (power), H22 IO_L7P_D19_LC_1 (io), J14 IO_L4P_D25_LC_1 (io), J15 IO_L20N_VREF_LC_1 (io), J20 IO_L19P_LC_1 (io), J21 IO_L7N_D18_LC_1 (io), K14 IO_L4N_D24_VREF_LC_1 (io), K15 VCCO_1 (power), K16 IO_L18P_VRN_LC_1 (io), L14 IO_L2N_D28_LC_1 (io), L15 IO_L2P_D29_LC_1 (io), L16 IO_L18N_VRP_LC_1 (io), L18 IO_L9N_GC_LC_1 (io), L19 IO_L19N_LC_1 (io), M16 IO_L16P_GC_CC_LC_1 (io), M17 IO_L10P_GC_LC_1 (io), M18 IO_L9P_GC_LC_1 (io), M19 VCCO_1 (power), M20 IO_L5N_D22_LC_1 (io), N15 IO_L16N_GC_CC_LC_1 (io), N16 VCCO_1 (power), N17 IO_L10N_GC_LC_1 (io), N18 IO_L1N_D30_LC_1 (io), N19 IO_L1P_D31_LC_1 (io), N20 IO_L5P_D23_LC_1 (io)
part B pins: AE16 IO_L6N_GC_LC_4 (io), AE17 IO_L6P_GC_LC_4 (io), AE18 IO_L1N_GC_LC_4 (io), AF16 IO_L2N_GC_LC_4 (io), AF17 VCCO_4 (power), AF18 IO_L1P_GC_LC_4 (io), AG16 IO_L2P_GC_LC_4 (io), AG17 IO_L5N_GC_LC_4 (io), AG18 IO_L5P_GC_LC_4 (io), AH17 IO_L8N_GC_CC_LC_4 (io), AH18 IO_L3N_GC_LC_4 (io), AH19 IO_L3P_GC_LC_4 (io), AJ17 IO_L8P_GC_CC_LC_4 (io), AJ18 VCCO_4 (power), AJ19 IO_L7P_GC_VRN_LC_4 (io), AK17 IO_L4N_GC_VREF_LC_4 (io), AK18 IO_L4P_GC_LC_4 (io), AK19 IO_L7N_GC_VRP_LC_4 (io), E16 IO_L6P_GC_LC_3 (io), E17 IO_L4N_GC_VREF_LC_3 (io), E18 IO_L4P_GC_LC_3 (io), F16 IO_L6N_GC_LC_3 (io), F17 VCCO_3 (power), F18 IO_L1P_GC_CC_LC_3 (io), G16 IO_L8N_GC_LC_3 (io), G17 IO_L8P_GC_LC_3 (io), G18 IO_L1N_GC_CC_LC_3 (io), H17 IO_L2P_GC_VRN_LC_3 (io), H18 IO_L3N_GC_LC_3 (io), H19 IO_L3P_GC_LC_3 (io), J17 IO_L2N_GC_VRP_LC_3 (io), J18 VCCO_3 (power), J19 IO_L7N_GC_LC_3 (io), K17 IO_L5N_GC_LC_3 (io), K18 IO_L5P_GC_LC_3 (io), K19 IO_L7P_GC_LC_3 (io)
part C pins: A2 VCCO_6 (power), A3 IO_L20N_VREF_6 (io), A4 IO_L20P_6 (io), A5 IO_L22P_6 (io), A6 IO_L12P_6 (io), A8 IO_L10P_6 (io), A9 IO_L15N_6 (io), A10 IO_L15P_6 (io), A11 IO_L3P_6 (io), A12 VCCO_6 (power), A13 IO_L17N_6 (io), A14 IO_L17P_6 (io), A21 IO_L21N_5 (io), A22 VCCO_5 (power), A23 IO_L1N_ADC7_5 (io), A24 IO_L3P_ADC5_5 (io), A25 IO_L3N_ADC5_5 (io), A26 IO_L2P_ADC6_5 (io), A28 IO_L14P_5 (io), A29 IO_L14N_5 (io), A30 IO_L18P_5 (io), A31 IO_L24P_CC_LC_5 (io), A32 VCCO_5 (power), B2 IO_L30N_6 (io), B3 IO_L30P_6 (io), B5 IO_L22N_6 (io), B6 IO_L12N_VREF_6 (io), B7 IO_L14P_6 (io), B8 IO_L10N_6 (io), B9 VCCO_6 (power), B10 IO_L2P_6 (io), B11 IO_L3N_6 (io), B12 IO_L9N_CC_LC_6 (io), B13 IO_L9P_CC_LC_6 (io), B21 IO_L21P_5 (io), B22 IO_L17N_5 (io), B23 IO_L1P_ADC7_5 (io), B25 IO_L15P_5 (io), B26 IO_L2N_ADC6_5 (io), B27 IO_L8P_CC_ADC1_LC_5 (io), B28 IO_L25P_CC_LC_5 (io), B29 VCCO_5 (power), B30 IO_L18N_5 (io), B31 IO_L24N_CC_LC_5 (io), B32 IO_L31P_5 (io), B33 IO_L31N_5 (io), C5 IO_L27P_6 (io), C6 VCCO_6 (power), C7 IO_L14N_6 (io), C8 IO_L4N_VREF_6 (io), C9 IO_L4P_6 (io), C10 IO_L2N_6 (io), C12 IO_L1N_6 (io), C13 IO_L25N_CC_LC_6 (io), C14 IO_L25P_CC_LC_6 (io), C22 IO_L17P_5 (io), C23 IO_L5P_ADC4_5 (io), C24 IO_L5N_ADC4_5 (io), C25 IO_L15N_5 (io), C26 VCCO_5 (power), C27 IO_L8N_CC_ADC1_LC_5 (io), C28 IO_L25N_CC_LC_5 (io), C29 IO_L20P_5 (io), C30 IO_L20N_VREF_5 (io), D5 IO_L27N_6 (io), D6 IO_L18N_6 (io), D7 IO_L18P_6 (io), D9 IO_L19P_6 (io), D10 IO_L7N_6 (io), D11 IO_L7P_6 (io), D12 IO_L1P_6 (io), D13 VCCO_6 (power), D14 IO_L29N_6 (io), D22 IO_L23N_VRP_5 (io), D23 VCCO_5 (power), D24 IO_L7P_ADC2_5 (io), D25 IO_L7N_ADC2_5 (io), D26 IO_L10P_5 (io), D27 IO_L12P_5 (io), D29 IO_L29P_5 (io), D30 IO_L26P_5 (io), D31 IO_L26N_5 (io), E6 IO_L26P_6 (io), E7 IO_L23N_VRP_6 (io), E8 IO_L23P_VRN_6 (io), E9 IO_L19N_6 (io), E10 VCCO_6 (power), E11 IO_L11P_6 (io), E12 IO_L21N_6 (io), E13 IO_L21P_6 (io), E14 IO_L29P_6 (io), E22 IO_L23P_VRN_5 (io), E23 IO_L9N_CC_LC_5 (io), E24 IO_L11N_5 (io), E26 IO_L10N_5 (io), E27 IO_L12N_VREF_5 (io), E28 IO_L22P_5 (io), E29 IO_L29N_5 (io), E30 VCCO_5 (power), E31 IO_L32P_5 (io), F6 IO_L26N_6 (io), F7 VCCO_6 (power), F8 IO_L16P_6 (io), F10 IO_L6P_6 (io), F11 IO_L11N_6 (io), F23 IO_L9P_CC_LC_5 (io), F24 IO_L11P_5 (io), F25 IO_L6P_ADC3_5 (io), F26 IO_L6N_ADC3_5 (io), F27 VCCO_5 (power), F28 IO_L22N_5 (io), F29 IO_L28P_5 (io), F30 IO_L28N_VREF_5 (io), F31 IO_L32N_5 (io), G6 IO_L28N_VREF_6 (io), G7 IO_L28P_6 (io), G8 IO_L16N_6 (io), G10 IO_L6N_6 (io), G11 IO_L5N_6 (io), G12 IO_L5P_6 (io), G23 IO_L13P_5 (io), G24 VCCO_5 (power), G25 IO_L4P_5 (io), G27 IO_L27P_5 (io), G28 IO_L27N_5 (io), H7 IO_L31N_6 (io), H8 IO_L31P_6 (io), H9 IO_L8N_CC_LC_6 (io), H10 IO_L8P_CC_LC_6 (io), H11 VCCO_6 (power), H12 IO_L13P_6 (io), H24 IO_L13N_5 (io), H25 IO_L4N_VREF_5 (io), J7 IO_L32N_6 (io), J8 VCCO_6 (power), J9 IO_L24P_CC_LC_6 (io), J11 IO_L13N_6 (io), J24 IO_L19N_5 (io), J25 IO_L16P_5 (io), K8 IO_L32P_6 (io), K9 IO_L24N_CC_LC_6 (io), K24 IO_L19P_5 (io), K25 VCCO_5 (power), K26 IO_L16N_5 (io), L25 IO_L30P_5 (io), L26 IO_L30N_5 (io)
part D pins: AD9 IO_L4N_VREF_8 (io), AD10 IO_L4P_8 (io), AE9 IO_L20N_VREF_8 (io), AE10 VCCO_8 (power), AE11 IO_L26P_8 (io), AE26 IO_L3N_7 (io), AE27 IO_L2N_7 (io), AF10 IO_L20P_8 (io), AF11 IO_L26N_8 (io), AF24 IO_L21N_7 (io), AF26 IO_L3P_7 (io), AF27 VCCO_7 (power), AF28 IO_L2P_7 (io), AG10 IO_L30N_8 (io), AG11 IO_L17N_8 (io), AG23 IO_L21P_7 (io), AG24 VCCO_7 (power), AG25 IO_L22P_7 (io), AG26 IO_L22N_7 (io), AG27 IO_L8P_CC_LC_7 (io), AG28 IO_L8N_CC_LC_7 (io), AH7 IO_L12N_VREF_8 (io), AH8 IO_L12P_8 (io), AH10 IO_L30P_8 (io), AH11 VCCO_8 (power), AH12 IO_L17P_8 (io), AH23 IO_L23P_VRN_7 (io), AH24 IO_L23N_VRP_7 (io), AH25 IO_L28N_VREF_7 (io), AH27 IO_L16N_7 (io), AH28 IO_L6P_7 (io), AH29 IO_L6N_7 (io), AJ4 IO_L2N_8 (io), AJ5 IO_L6N_8 (io), AJ6 IO_L6P_8 (io), AJ7 IO_L7N_8 (io), AJ8 VCCO_8 (power), AJ9 IO_L15N_8 (io), AJ10 IO_L15P_8 (io), AJ11 IO_L23P_VRN_8 (io), AJ12 IO_L21P_8 (io), AJ24 IO_L19N_7 (io), AJ25 IO_L28P_7 (io), AJ27 IO_L16P_7 (io), AJ28 VCCO_7 (power), AJ29 IO_L1N_7 (io), AK4 IO_L2P_8 (io), AK5 VCCO_8 (power), AK6 IO_L10N_8 (io), AK7 IO_L7P_8 (io), AK8 IO_L11N_8 (io), AK9 IO_L28N_VREF_8 (io), AK11 IO_L23N_VRP_8 (io), AK12 IO_L21N_8 (io), AK13 IO_L9P_CC_LC_8 (io), AK21 IO_L5P_7 (io), AK22 IO_L13P_7 (io), AK23 IO_L13N_7 (io), AK24 IO_L19P_7 (io), AK25 VCCO_7 (power), AK26 IO_L26N_SM6_7 (io), AK27 IO_L20P_7 (io), AK28 IO_L20N_VREF_7 (io), AK29 IO_L1P_7 (io), AL4 IO_L1N_8 (io), AL5 IO_L1P_8 (io), AL6 IO_L10P_8 (io), AL8 IO_L11P_8 (io), AL9 IO_L28P_8 (io), AL10 IO_L25N_CC_LC_8 (io), AL11 IO_L25P_CC_LC_8 (io), AL12 VCCO_8 (power), AL13 IO_L9N_CC_LC_8 (io), AL21 IO_L5N_7 (io), AL22 VCCO_7 (power), AL23 IO_L31P_SM2_7 (io), AL24 IO_L25P_CC_SM7_LC_7 (io), AL25 IO_L25N_CC_SM7_LC_7 (io), AL26 IO_L26P_SM6_7 (io), AL28 IO_L14P_7 (io), AL29 IO_L14N_7 (io), AL30 IO_L10N_7 (io), AM5 IO_L14N_8 (io), AM6 IO_L14P_8 (io), AM7 IO_L18N_8 (io), AM8 IO_L22N_8 (io), AM9 VCCO_8 (power), AM10 IO_L19N_8 (io), AM11 IO_L27N_8 (io), AM12 IO_L27P_8 (io), AM13 IO_L13P_8 (io), AM21 IO_L9P_CC_LC_7 (io), AM22 IO_L9N_CC_LC_7 (io), AM23 IO_L31N_SM2_7 (io), AM25 IO_L32N_SM1_7 (io), AM26 IO_L30P_SM3_7 (io), AM27 IO_L30N_SM3_7 (io), AM28 IO_L24N_CC_LC_7 (io), AM29 VCCO_7 (power), AM30 IO_L10P_7 (io), AN2 IO_L8N_CC_LC_8 (io), AN3 IO_L8P_CC_LC_8 (io), AN4 IO_L3N_8 (io), AN5 IO_L16N_8 (io), AN6 VCCO_8 (power), AN7 IO_L18P_8 (io), AN8 IO_L22P_8 (io), AN9 IO_L32N_8 (io), AN10 IO_L19P_8 (io), AN12 IO_L31P_8 (io), AN13 IO_L13N_8 (io), AN14 IO_L5P_8 (io), AN22 IO_L27P_SM5_7 (io), AN23 IO_L27N_SM5_7 (io), AN24 IO_L29N_SM4_7 (io), AN25 IO_L32P_SM1_7 (io), AN26 VCCO_7 (power), AN27 IO_L11N_7 (io), AN28 IO_L24P_CC_LC_7 (io), AN29 IO_L18N_7 (io), AN30 IO_L7N_7 (io), AN32 IO_L4P_7 (io), AN33 IO_L4N_VREF_7 (io), AP3 VCCO_8 (power), AP4 IO_L3P_8 (io), AP5 IO_L16P_8 (io), AP6 IO_L24N_CC_LC_8 (io), AP7 IO_L24P_CC_LC_8 (io), AP9 IO_L32P_8 (io), AP10 IO_L29N_8 (io), AP11 IO_L29P_8 (io), AP12 IO_L31N_8 (io), AP13 VCCO_8 (power), AP14 IO_L5N_8 (io), AP21 IO_L17P_7 (io), AP22 IO_L17N_7 (io), AP23 VCCO_7 (power), AP24 IO_L29P_SM4_7 (io), AP25 IO_L15P_7 (io), AP26 IO_L15N_7 (io), AP27 IO_L11P_7 (io), AP29 IO_L18P_7 (io), AP30 IO_L7P_7 (io), AP31 IO_L12P_7 (io), AP32 IO_L12N_VREF_7 (io), AP33 VCCO_7 (power)
part E pins: C2 IO_L7P_10 (io), C3 IO_L1N_10 (io), C4 IO_L1P_10 (io), C32 IO_L2P_9 (io), C33 IO_L7P_9 (io), C34 IO_L7N_9 (io), D1 IO_L8P_CC_LC_10 (io), D2 IO_L7N_10 (io), D3 VCCO_10 (power), D4 IO_L3P_10 (io), D32 IO_L2N_9 (io), D33 VCCO_9 (power), D34 IO_L8P_CC_LC_9 (io), E1 IO_L8N_CC_LC_10 (io), E2 IO_L9N_CC_LC_10 (io), E3 IO_L9P_CC_LC_10 (io), E4 IO_L3N_10 (io), E32 IO_L11P_9 (io), E33 IO_L11N_9 (io), E34 IO_L8N_CC_LC_9 (io), F1 IO_L17P_10 (io), F3 IO_L6N_10 (io), F4 IO_L6P_10 (io), F5 IO_L2P_10 (io), F33 IO_L14P_9 (io), F34 IO_L14N_9 (io), G1 IO_L17N_10 (io), G2 IO_L14N_10 (io), G3 IO_L14P_10 (io), G4 VCCO_10 (power), G5 IO_L2N_10 (io), G30 IO_L9P_CC_LC_9 (io), G31 IO_L9N_CC_LC_9 (io), G32 IO_L16P_9 (io), G33 IO_L16N_9 (io), G34 VCCO_9 (power), H1 VCCO_10 (power), H2 IO_L19N_10 (io), H3 IO_L19P_10 (io), H4 IO_L11N_10 (io), H5 IO_L11P_10 (io), H27 IO_L1P_9 (io), H28 IO_L1N_9 (io), H29 IO_L6P_9 (io), H30 IO_L6N_9 (io), H31 VCCO_9 (power), H32 IO_L20P_9 (io), H33 IO_L22P_9 (io), H34 IO_L22N_9 (io), J1 IO_L23N_VRP_10 (io), J2 IO_L23P_VRN_10 (io), J4 IO_L18P_10 (io), J5 IO_L10N_10 (io), J6 IO_L10P_10 (io), J27 IO_L3P_9 (io), J28 VCCO_9 (power), J29 IO_L10P_9 (io), J30 IO_L10N_9 (io), J31 IO_L23P_VRN_9 (io), J32 IO_L20N_VREF_9 (io), J34 IO_L29P_9 (io), K1 IO_L26N_10 (io), K2 IO_L26P_10 (io), K3 IO_L25P_CC_LC_10 (io), K4 IO_L18N_10 (io), K5 VCCO_10 (power), K6 IO_L16P_10 (io), K27 IO_L3N_9 (io), K28 IO_L15P_9 (io), K29 IO_L15N_9 (io), K31 IO_L23N_VRP_9 (io), K32 IO_L26P_9 (io), K33 IO_L26N_9 (io), K34 IO_L29N_9 (io), L1 IO_L29P_10 (io), L2 VCCO_10 (power), L3 IO_L25N_CC_LC_10 (io), L4 IO_L22N_10 (io), L5 IO_L22P_10 (io), L6 IO_L16N_10 (io), L8 IO_L15P_10 (io), L9 IO_L4N_VREF_10 (io), L28 IO_L18P_9 (io), L29 IO_L18N_9 (io), L30 IO_L24P_CC_LC_9 (io), L31 IO_L24N_CC_LC_9 (io), L32 VCCO_9 (power), L33 IO_L31P_9 (io), L34 IO_L31N_9 (io), M1 IO_L29N_10 (io), M2 IO_L28N_VREF_10 (io), M3 IO_L28P_10 (io), M5 IO_L27N_10 (io), M6 IO_L27P_10 (io), M7 IO_L21P_10 (io), M8 IO_L15N_10 (io), M9 VCCO_10 (power), M10 IO_L4P_10 (io), M25 IO_L4P_9 (io), M26 IO_L4N_VREF_9 (io), M27 IO_L21P_9 (io), M28 IO_L21N_9 (io), M29 VCCO_9 (power), M30 IO_L28P_9 (io), M31 IO_L28N_VREF_9 (io), M32 IO_L32P_9 (io), M33 IO_L32N_9 (io), N5 IO_L30P_10 (io), N6 VCCO_10 (power), N7 IO_L21N_10 (io), N9 IO_L12N_VREF_10 (io), N10 IO_L12P_10 (io), N12 IO_L5N_10 (io), N13 IO_L5P_10 (io), N22 IO_L5P_9 (io), N23 IO_L5N_9 (io), N25 IO_L12P_9 (io), N26 VCCO_9 (power), N27 IO_L27P_9 (io), N29 IO_L30P_9 (io), N30 IO_L30N_9 (io), P5 IO_L30N_10 (io), P6 IO_L31N_10 (io), P7 IO_L31P_10 (io), P9 IO_L20N_VREF_10 (io), P10 IO_L20P_10 (io), P11 IO_L13N_10 (io), P12 IO_L13P_10 (io), P13 VCCO_10 (power), P20 IO_L17P_9 (io), P22 IO_L13P_9 (io), P23 VCCO_9 (power), P24 IO_L19P_9 (io), P26 IO_L12N_VREF_9 (io), P27 IO_L27N_9 (io), R9 IO_L32N_10 (io), R10 VCCO_10 (power), R11 IO_L24P_CC_LC_10 (io), R19 IO_L17N_9 (io), R20 VCCO_9 (power), R21 IO_L13N_9 (io), R22 IO_L25P_CC_LC_9 (io), R23 IO_L25N_CC_LC_9 (io), R24 IO_L19N_9 (io), T10 IO_L32P_10 (io), T11 IO_L24N_CC_LC_10 (io)
part F pins: AA8 IO_L8N_CC_LC_12 (io), AA9 IO_L8P_CC_LC_12 (io), AA11 IO_L3N_12 (io), AA12 VCCO_12 (power), AA13 IO_L5N_12 (io), AA15 IO_L13N_12 (io), AA22 VCCO_11 (power), AA23 IO_L17P_11 (io), AA24 IO_L17N_11 (io), AA25 IO_L9P_CC_LC_11 (io), AA26 IO_L9N_CC_LC_11 (io), AA28 IO_L1P_11 (io), AA29 IO_L1N_11 (io), AA30 IO_L3N_11 (io), AB5 IO_L1N_12 (io), AB6 IO_L1P_12 (io), AB8 IO_L12N_VREF_12 (io), AB9 VCCO_12 (power), AB10 IO_L25N_CC_LC_12 (io), AB12 IO_L29N_12 (io), AB13 IO_L29P_12 (io), AB22 IO_L29P_11 (io), AB23 IO_L29N_11 (io), AB25 IO_L20P_11 (io), AB26 IO_L20N_VREF_11 (io), AB28 IO_L11N_11 (io), AB29 VCCO_11 (power), AB30 IO_L3P_11 (io), AC2 IO_L2N_12 (io), AC3 IO_L2P_12 (io), AC4 IO_L6N_12 (io), AC5 IO_L6P_12 (io), AC6 VCCO_12 (power), AC7 IO_L12P_12 (io), AC8 IO_L17N_12 (io), AC9 IO_L17P_12 (io), AC10 IO_L25P_CC_LC_12 (io), AC25 IO_L23P_VRN_11 (io), AC26 VCCO_11 (power), AC27 IO_L19N_11 (io), AC28 IO_L11P_11 (io), AC29 IO_L7P_11 (io), AC30 IO_L7N_11 (io), AC32 IO_L6P_11 (io), AC33 IO_L6N_11 (io), AC34 IO_L8N_CC_LC_11 (io), AD1 IO_L4N_VREF_12 (io), AD2 IO_L4P_12 (io), AD3 VCCO_12 (power), AD4 IO_L14N_12 (io), AD5 IO_L11N_12 (io), AD6 IO_L11P_12 (io), AD7 IO_L24N_CC_LC_12 (io), AD26 IO_L23N_VRP_11 (io), AD27 IO_L19P_11 (io), AD29 IO_L15N_11 (io), AD30 IO_L12P_11 (io), AD31 IO_L12N_VREF_11 (io), AD32 IO_L10N_11 (io), AD33 VCCO_11 (power), AD34 IO_L8P_CC_LC_11 (io), AE1 IO_L7N_12 (io), AE2 IO_L10N_12 (io), AE3 IO_L10P_12 (io), AE4 IO_L14P_12 (io), AE6 IO_L19N_12 (io), AE7 IO_L24P_CC_LC_12 (io), AE8 IO_L27N_12 (io), AE29 IO_L15P_11 (io), AE30 VCCO_11 (power), AE31 IO_L16N_11 (io), AE32 IO_L10P_11 (io), AE33 IO_L5P_11 (io), AE34 IO_L5N_11 (io), AF1 IO_L7P_12 (io), AF3 IO_L18N_12 (io), AF4 IO_L20N_VREF_12 (io), AF5 IO_L20P_12 (io), AF6 IO_L19P_12 (io), AF7 VCCO_12 (power), AF8 IO_L27P_12 (io), AF29 IO_L24P_CC_LC_11 (io), AF30 IO_L24N_CC_LC_11 (io), AF31 IO_L16P_11 (io), AF33 IO_L14P_11 (io), AF34 IO_L14N_11 (io), AG1 IO_L16N_12 (io), AG2 IO_L16P_12 (io), AG3 IO_L18P_12 (io), AG4 VCCO_12 (power), AG5 IO_L23N_VRP_12 (io), AG6 IO_L23P_VRN_12 (io), AG7 IO_L31N_12 (io), AG8 IO_L31P_12 (io), AG30 IO_L21P_11 (io), AG31 IO_L21N_11 (io), AG32 IO_L13P_11 (io), AG33 IO_L13N_11 (io), AG34 VCCO_11 (power), AH1 VCCO_12 (power), AH2 IO_L15N_12 (io), AH3 IO_L15P_12 (io), AH4 IO_L28N_VREF_12 (io), AH5 IO_L28P_12 (io), AH30 IO_L32N_11 (io), AH31 VCCO_11 (power), AH32 IO_L22P_11 (io), AH33 IO_L22N_11 (io), AH34 IO_L18N_11 (io), AJ1 IO_L22N_12 (io), AJ2 IO_L22P_12 (io), AJ30 IO_L32P_11 (io), AJ31 IO_L28P_11 (io), AJ32 IO_L28N_VREF_11 (io), AJ34 IO_L18P_11 (io), AK1 IO_L21N_12 (io), AK2 IO_L26N_12 (io), AK3 IO_L26P_12 (io), AK31 IO_L25P_CC_LC_11 (io), AK32 IO_L25N_CC_LC_11 (io), AK33 IO_L26P_11 (io), AK34 IO_L26N_11 (io), AL1 IO_L21P_12 (io), AL2 VCCO_12 (power), AL3 IO_L32N_12 (io), AL31 IO_L31N_11 (io), AL32 VCCO_11 (power), AL33 IO_L30P_11 (io), AL34 IO_L30N_11 (io), AM1 IO_L30N_12 (io), AM2 IO_L30P_12 (io), AM3 IO_L32P_12 (io), AM31 IO_L31P_11 (io), AM32 IO_L27P_11 (io), AM33 IO_L27N_11 (io), W24 IO_L2P_11 (io), W25 IO_L4P_11 (io), Y11 IO_L3P_12 (io), Y12 IO_L9N_CC_LC_12 (io), Y13 IO_L9P_CC_LC_12 (io), Y14 IO_L5P_12 (io), Y15 VCCO_12 (power), Y16 IO_L13P_12 (io), Y24 IO_L2N_11 (io), Y25 VCCO_11 (power), Y26 IO_L4N_VREF_11 (io)
part G pins: AA1 IO_L26P_14 (io), AA2 VCCO_14 (power), AA3 IO_L27N_14 (io), AA4 IO_L25N_CC_LC_14 (io), AA5 IO_L25P_CC_LC_14 (io), AA6 IO_L29P_14 (io), AA31 IO_L31N_13 (io), AA32 VCCO_13 (power), AA33 IO_L30P_13 (io), AA34 IO_L30N_13 (io), AB1 IO_L28N_VREF_14 (io), AB2 IO_L28P_14 (io), AB3 IO_L27P_14 (io), AB31 IO_L31P_13 (io), AB32 IO_L29P_13 (io), AB33 IO_L29N_13 (io), N2 IO_L2N_14 (io), N3 IO_L2P_14 (io), N4 IO_L1P_14 (io), N32 IO_L6P_13 (io), N33 IO_L8P_CC_LC_13 (io), N34 IO_L8N_CC_LC_13 (io), P1 IO_L5N_14 (io), P2 IO_L5P_14 (io), P3 VCCO_14 (power), P4 IO_L1N_14 (io), P29 IO_L5P_13 (io), P30 IO_L7P_13 (io), P31 IO_L7N_13 (io), P32 IO_L6N_13 (io), P33 VCCO_13 (power), P34 IO_L9P_CC_LC_13 (io), R1 IO_L8P_CC_LC_14 (io), R2 IO_L7N_14 (io), R3 IO_L7P_14 (io), R4 IO_L6P_14 (io), R6 IO_L4N_VREF_14 (io), R7 IO_L4P_14 (io), R8 IO_L3P_14 (io), R26 IO_L2P_13 (io), R27 IO_L4P_13 (io), R28 IO_L4N_VREF_13 (io), R29 IO_L5N_13 (io), R30 VCCO_13 (power), R31 IO_L10P_13 (io), R32 IO_L11P_13 (io), R33 IO_L11N_13 (io), R34 IO_L9N_CC_LC_13 (io), T1 IO_L8N_CC_LC_14 (io), T3 IO_L10P_14 (io), T4 IO_L6N_14 (io), T5 IO_L9N_CC_LC_14 (io), T6 IO_L9P_CC_LC_14 (io), T7 VCCO_14 (power), T8 IO_L3N_14 (io), T23 IO_L1P_13 (io), T24 IO_L3P_13 (io), T25 IO_L3N_13 (io), T26 IO_L2N_13 (io), T27 VCCO_13 (power), T28 IO_L12P_13 (io), T29 IO_L13P_13 (io), T30 IO_L13N_13 (io), T31 IO_L10N_13 (io), T33 IO_L14P_13 (io), T34 IO_L14N_13 (io), U1 IO_L12N_VREF_14 (io), U2 IO_L12P_14 (io), U3 IO_L10N_14 (io), U4 VCCO_14 (power), U5 IO_L15N_14 (io), U6 IO_L15P_14 (io), U7 IO_L11N_14 (io), U8 IO_L11P_14 (io), U10 IO_L14P_14 (io), U11 IO_L13N_14 (io), U12 IO_L13P_14 (io), U23 IO_L1N_13 (io), U24 VCCO_13 (power), U25 IO_L19N_13 (io), U26 IO_L15P_13 (io), U27 IO_L15N_13 (io), U28 IO_L12N_VREF_13 (io), U30 IO_L16P_13 (io), U31 IO_L16N_13 (io), U32 IO_L18P_13 (io), U33 IO_L18N_13 (io), U34 VCCO_13 (power), V1 VCCO_14 (power), V2 IO_L16N_14 (io), V3 IO_L16P_14 (io), V4 IO_L18N_14 (io), V5 IO_L18P_14 (io), V7 IO_L22N_14 (io), V8 IO_L17N_14 (io), V9 IO_L17P_14 (io), V10 IO_L14N_14 (io), V11 VCCO_14 (power), V12 IO_L21P_14 (io), V23 IO_L21P_13 (io), V24 IO_L21N_13 (io), V25 IO_L19P_13 (io), V27 IO_L26N_13 (io), V28 IO_L20P_13 (io), V29 IO_L20N_VREF_13 (io), V30 IO_L24N_CC_LC_13 (io), V31 VCCO_13 (power), V32 IO_L22N_13 (io), V33 IO_L17P_13 (io), V34 IO_L17N_13 (io), W1 IO_L20N_VREF_14 (io), W2 IO_L20P_14 (io), W4 IO_L23N_VRP_14 (io), W5 IO_L19N_14 (io), W6 IO_L19P_14 (io), W7 IO_L22P_14 (io), W8 VCCO_14 (power), W9 IO_L31N_14 (io), W10 IO_L32N_14 (io), W11 IO_L32P_14 (io), W12 IO_L21N_14 (io), W27 IO_L26P_13 (io), W28 VCCO_13 (power), W29 IO_L27N_13 (io), W30 IO_L24P_CC_LC_13 (io), W31 IO_L28N_VREF_13 (io), W32 IO_L22P_13 (io), W34 IO_L23N_VRP_13 (io), Y1 IO_L26N_14 (io), Y2 IO_L24N_CC_LC_14 (io), Y3 IO_L24P_CC_LC_14 (io), Y4 IO_L23P_VRN_14 (io), Y5 VCCO_14 (power), Y6 IO_L29N_14 (io), Y7 IO_L30N_14 (io), Y8 IO_L30P_14 (io), Y9 IO_L31P_14 (io), Y27 IO_L32P_13 (io), Y28 IO_L32N_13 (io), Y29 IO_L27P_13 (io), Y31 IO_L28P_13 (io), Y32 IO_L25P_CC_LC_13 (io), Y33 IO_L25N_CC_LC_13 (io), Y34 IO_L23P_VRN_13 (io)
part H pins: D15 TDP_0, F15 TDN_0, R17 CCLK_0 (io), T16 D_IN_0 (in), T17 VCCO_0 (power), T18 HSWAPEN_0 (in), U13 RDWR_B_0 (in), U14 VCCO_0 (power), U15 DONE_0 (io), U17 CS_B_0 (in), U21 INIT_0 (io), U22 PROGRAM_B_0 (in), V13 TMS_0 (in), V14 TCK_0 (in), V18 TDO_0 (out), V20 M2_0 (in), V21 VCCO_0 (power), V22 VBATT_0 (power), W17 TDI_0 (in), W18 VCCO_0 (power), W19 M1_0 (in), W20 M0_0 (in), W21 PWRDWN_B_0 (in), Y18 DOUT_BUSY_0 (out)
part I pins: A16 AVSS_ADC (in), A17 VN_ADC (in), A18 VP_ADC (in), AA10 VCCAUX (power), AA16 VCCINT (power), AA18 VCCINT (power), AA20 VCCINT (power), AB7 VCCINT (power), AB11 VCCINT (power), AB21 VCCINT (power), AB27 VCCAUX (power), AC12 VCCINT (power), AC14 VCCINT (power), AC18 VCCINT (power), AC20 VCCINT (power), AC22 VCCINT (power), AC24 VCCAUX (power), AD11 VCCAUX (power), AD13 VCCINT (power), AD15 VCCINT (power), AD23 VCCINT (power), AD25 VCCINT (power), AE12 VCCINT (power), AE14 VCCINT (power), AE22 VCCINT (power), AE24 VCCINT (power), AE28 VCCINT (power), AF9 VCCINT (power), AF13 VCCINT (power), AF19 VCCINT (power), AF23 VCCINT (power), AF25 VCCAUX (power), AG12 VCCAUX (power), AH9 VCCAUX (power), AH13 VCCINT (power), AH15 VCCINT (power), AJ16 VCCAUX (power), AJ26 VCCAUX (power), AN17 VREFN_SM (in), AN18 VREFP_SM (in), AN19 AVSS_SM (in), AP17 VN_SM (in), AP18 VP_SM (in), AP19 AVDD_SM (in), B16 AVDD_ADC (in), B17 VREFN_ADC (in), B18 VREFP_ADC (in), F9 VCCAUX (power), F19 VCCAUX (power), G20 VCCINT (power), G22 VCCINT (power), G26 VCCAUX (power), H23 VCCAUX (power), J10 VCCAUX (power), J12 VCCINT (power), J16 VCCINT (power), J22 VCCINT (power), J26 VCCINT (power), K7 VCCINT (power), K11 VCCINT (power), K13 VCCINT (power), K21 VCCINT (power), K23 VCCINT (power), L10 VCCINT (power), L12 VCCINT (power), L20 VCCINT (power), L22 VCCINT (power), L24 VCCAUX (power), M11 VCCAUX (power), M13 VCCINT (power), M15 VCCINT (power), M21 VCCINT (power), M23 VCCINT (power), N8 VCCAUX (power), N14 VCCINT (power), N24 VCCINT (power), N28 VCCINT (power), P15 VCCINT (power), P17 VCCINT (power), P19 VCCINT (power), P25 VCCAUX (power), R12 VCCINT (power), R14 VCCINT (power), R16 VCCINT (power), R18 VCCAUX (power), T9 VCCAUX (power), T13 VCCINT (power), T15 VCCINT (power), T19 VCCINT (power), T21 VCCINT (power), U16 VCCAUX (power), U18 VCCINT (power), U20 VCCINT (power), V15 VCCINT (power), V17 VCCINT (power), V19 VCCAUX (power), W14 VCCINT (power), W16 VCCINT (power), W22 VCCINT (power), W26 VCCAUX (power), Y17 VCCAUX (power), Y19 VCCINT (power), Y21 VCCINT (power), Y23 VCCINT (power)
part J pins: A7 GND (power), A19 GND (power), A27 GND (power), A33 GND (power), AA7 GND (power), AA17 GND (power), AA19 GND (power), AA27 GND (power), AB4 GND (power), AB14 GND (power), AB20 GND (power), AB24 GND (power), AB34 GND (power), AC1 GND (power), AC11 GND (power), AC13 GND (power), AC21 GND (power), AC23 GND (power), AC31 GND (power), AD8 GND (power), AD12 GND (power), AD14 GND (power), AD18 GND (power), AD22 GND (power), AD24 GND (power), AD28 GND (power), AE5 GND (power), AE13 GND (power), AE15 GND (power), AE23 GND (power), AE25 GND (power), AF2 GND (power), AF12 GND (power), AF22 GND (power), AF32 GND (power), AG9 GND (power), AG19 GND (power), AG29 GND (power), AH6 GND (power), AH16 GND (power), AH26 GND (power), AJ3 GND (power), AJ13 GND (power), AJ23 GND (power), AJ33 GND (power), AK10 GND (power), AK20 GND (power), AK30 GND (power), AL7 GND (power), AL17 GND (power), AL27 GND (power), AM4 GND (power), AM14 GND (power), AM24 GND (power), AM34 GND (power), AN1 GND (power), AN11 GND (power), AN21 GND (power), AN31 GND (power), AN34 GND (power), AP2 GND (power), AP8 GND (power), AP16 GND (power), AP28 GND (power), B1 GND (power), B4 GND (power), B14 GND (power), B24 GND (power), B34 GND (power), C1 GND (power), C11 GND (power), C21 GND (power), C31 GND (power), D8 GND (power), D18 GND (power), D28 GND (power), E5 GND (power), E15 GND (power), E25 GND (power), F2 GND (power), F12 GND (power), F22 GND (power), F32 GND (power), G9 GND (power), G19 GND (power), G29 GND (power), H6 GND (power), H16 GND (power), H26 GND (power), J3 GND (power), J13 GND (power), J23 GND (power), J33 GND (power), K10 GND (power), K12 GND (power), K20 GND (power), K22 GND (power), K30 GND (power), L7 GND (power), L11 GND (power), L13 GND (power), L17 GND (power), L21 GND (power), L23 GND (power), L27 GND (power), M4 GND (power), M12 GND (power), M14 GND (power), M22 GND (power), M24 GND (power), M34 GND (power), N1 GND (power), N11 GND (power), N21 GND (power), N31 GND (power), P8 GND (power), P16 GND (power), P18 GND (power), P28 GND (power), R5 GND (power), R13 GND (power), R15 GND (power), R25 GND (power), T2 GND (power), T12 GND (power), T14 GND (power), T20 GND (power), T22 GND (power), T32 GND (power), U9 GND (power), U19 GND (power), U29 GND (power), V6 GND (power), V16 GND (power), V26 GND (power), W3 GND (power), W13 GND (power), W15 GND (power), W23 GND (power), W33 GND (power), Y10 GND (power), Y20 GND (power), Y22 GND (power), Y30 GND (power)

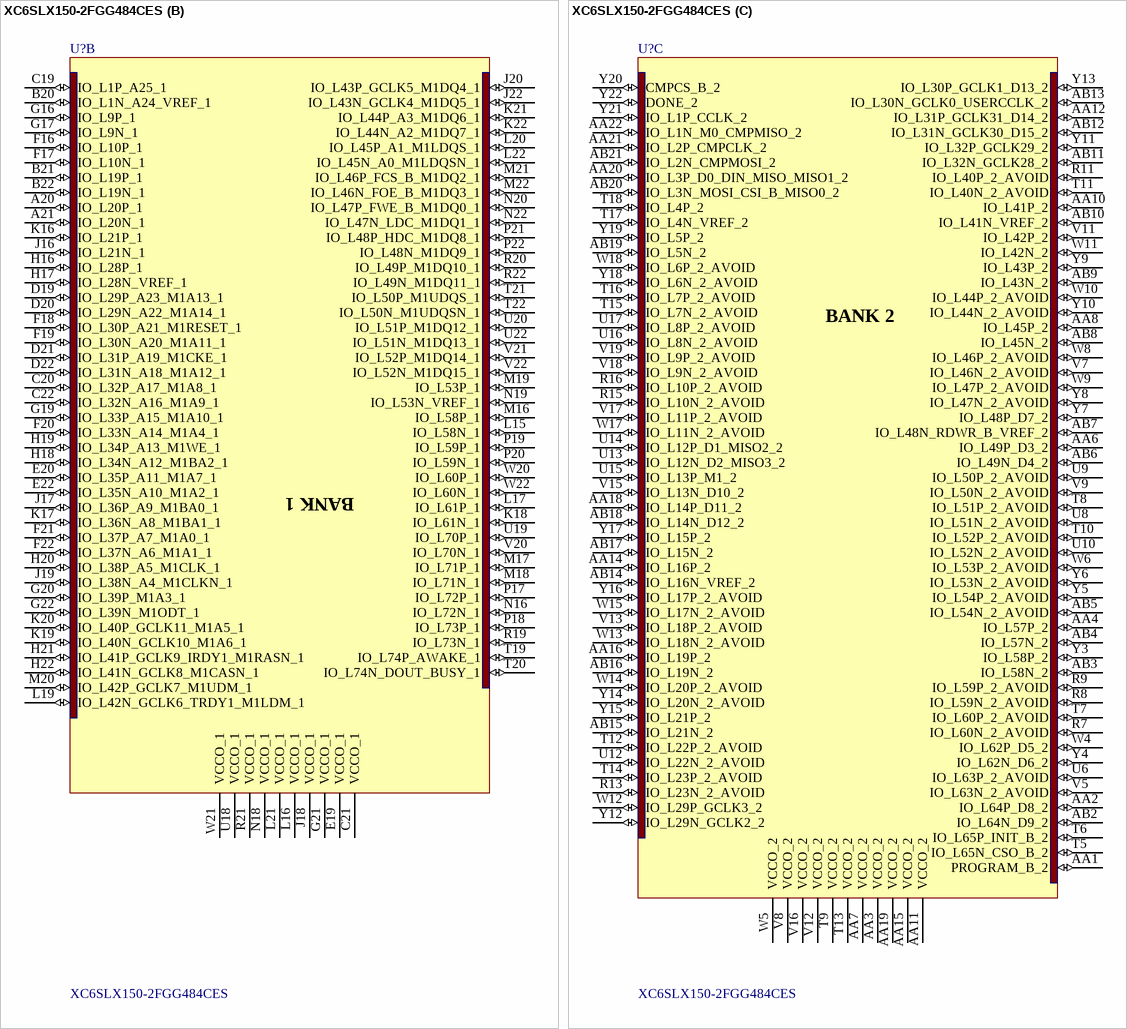
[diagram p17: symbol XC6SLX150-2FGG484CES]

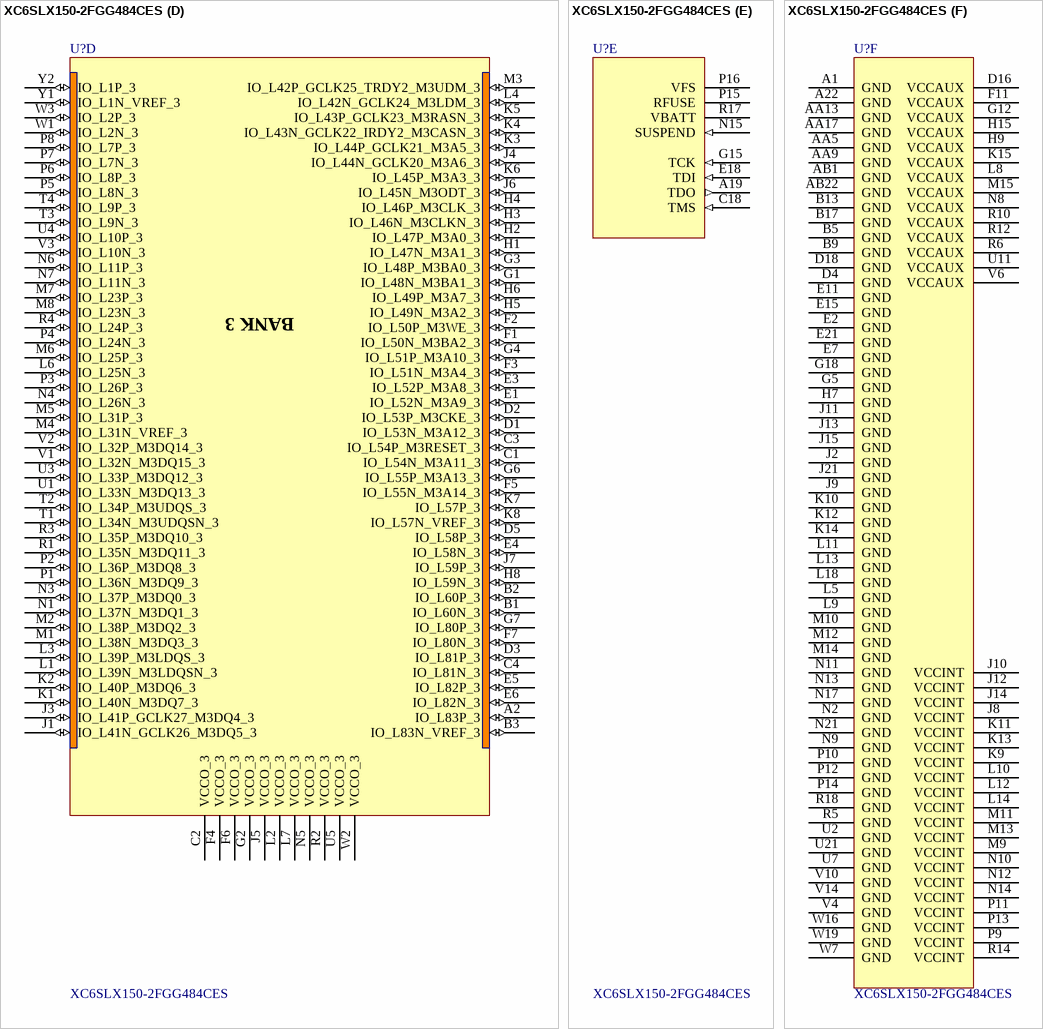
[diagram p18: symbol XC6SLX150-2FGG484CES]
